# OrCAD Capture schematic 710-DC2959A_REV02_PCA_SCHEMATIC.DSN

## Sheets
1 PAGE4: size Custom
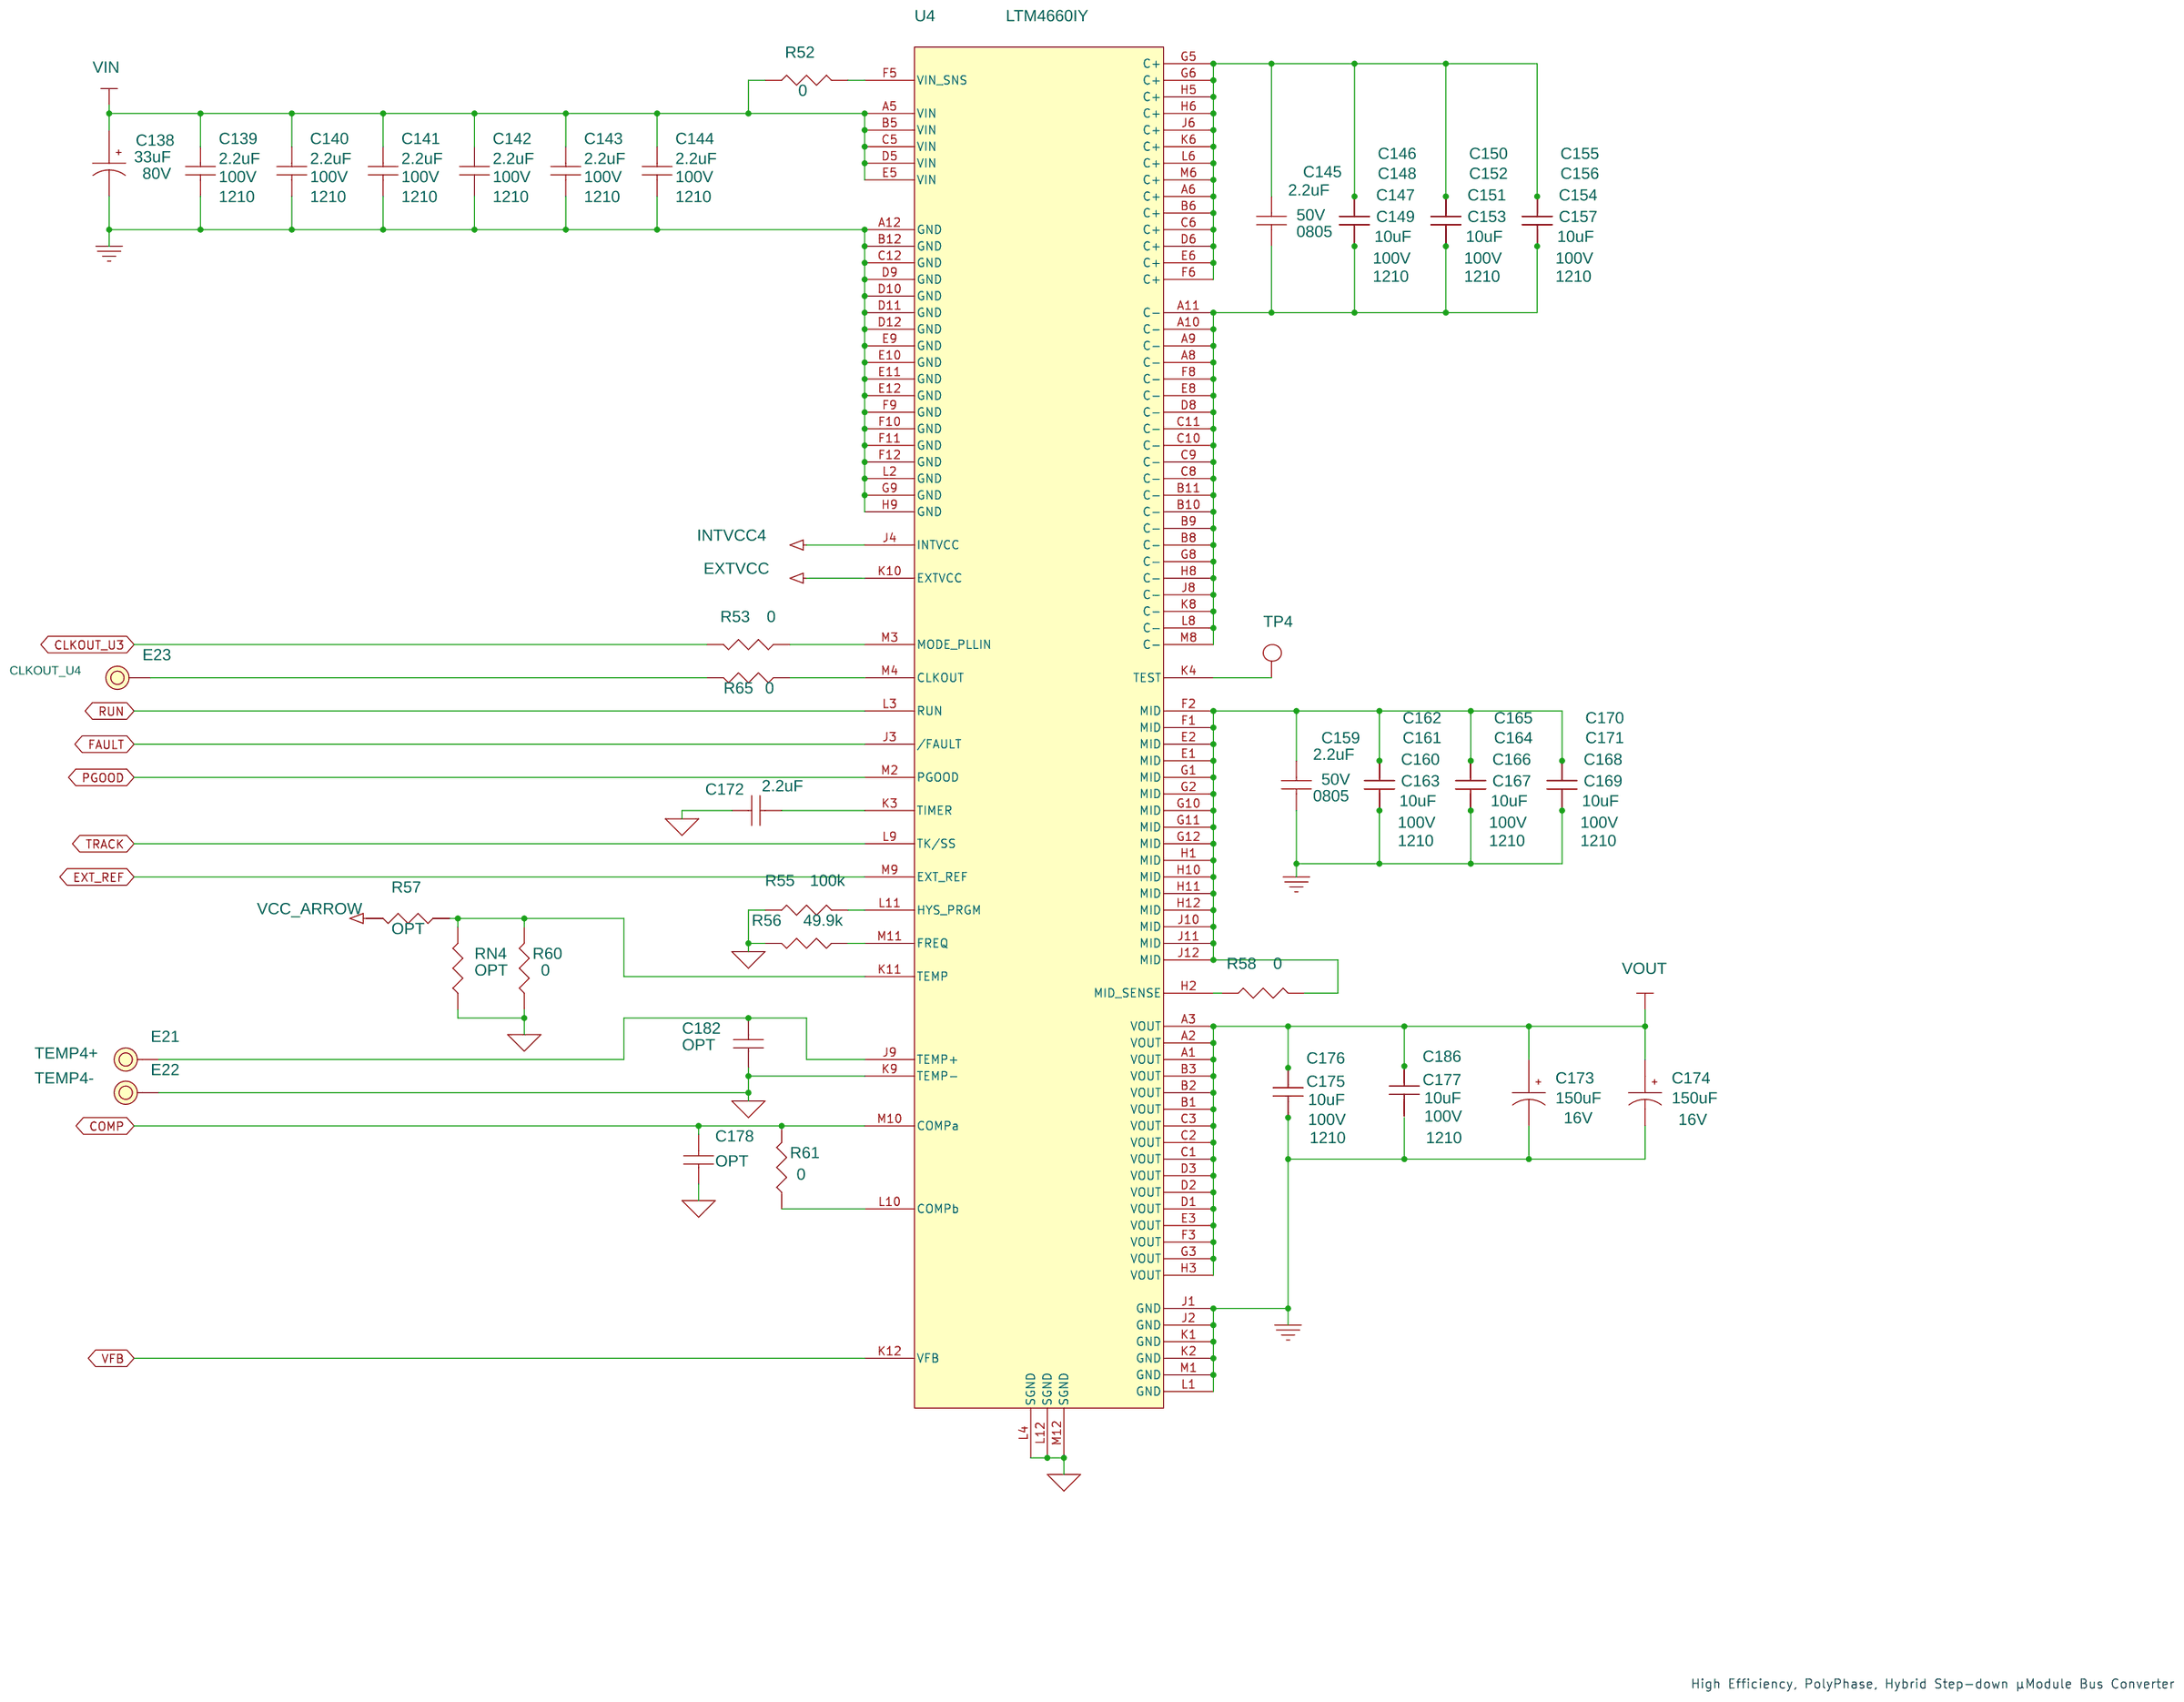
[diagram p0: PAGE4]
2 PAGE3: size Custom
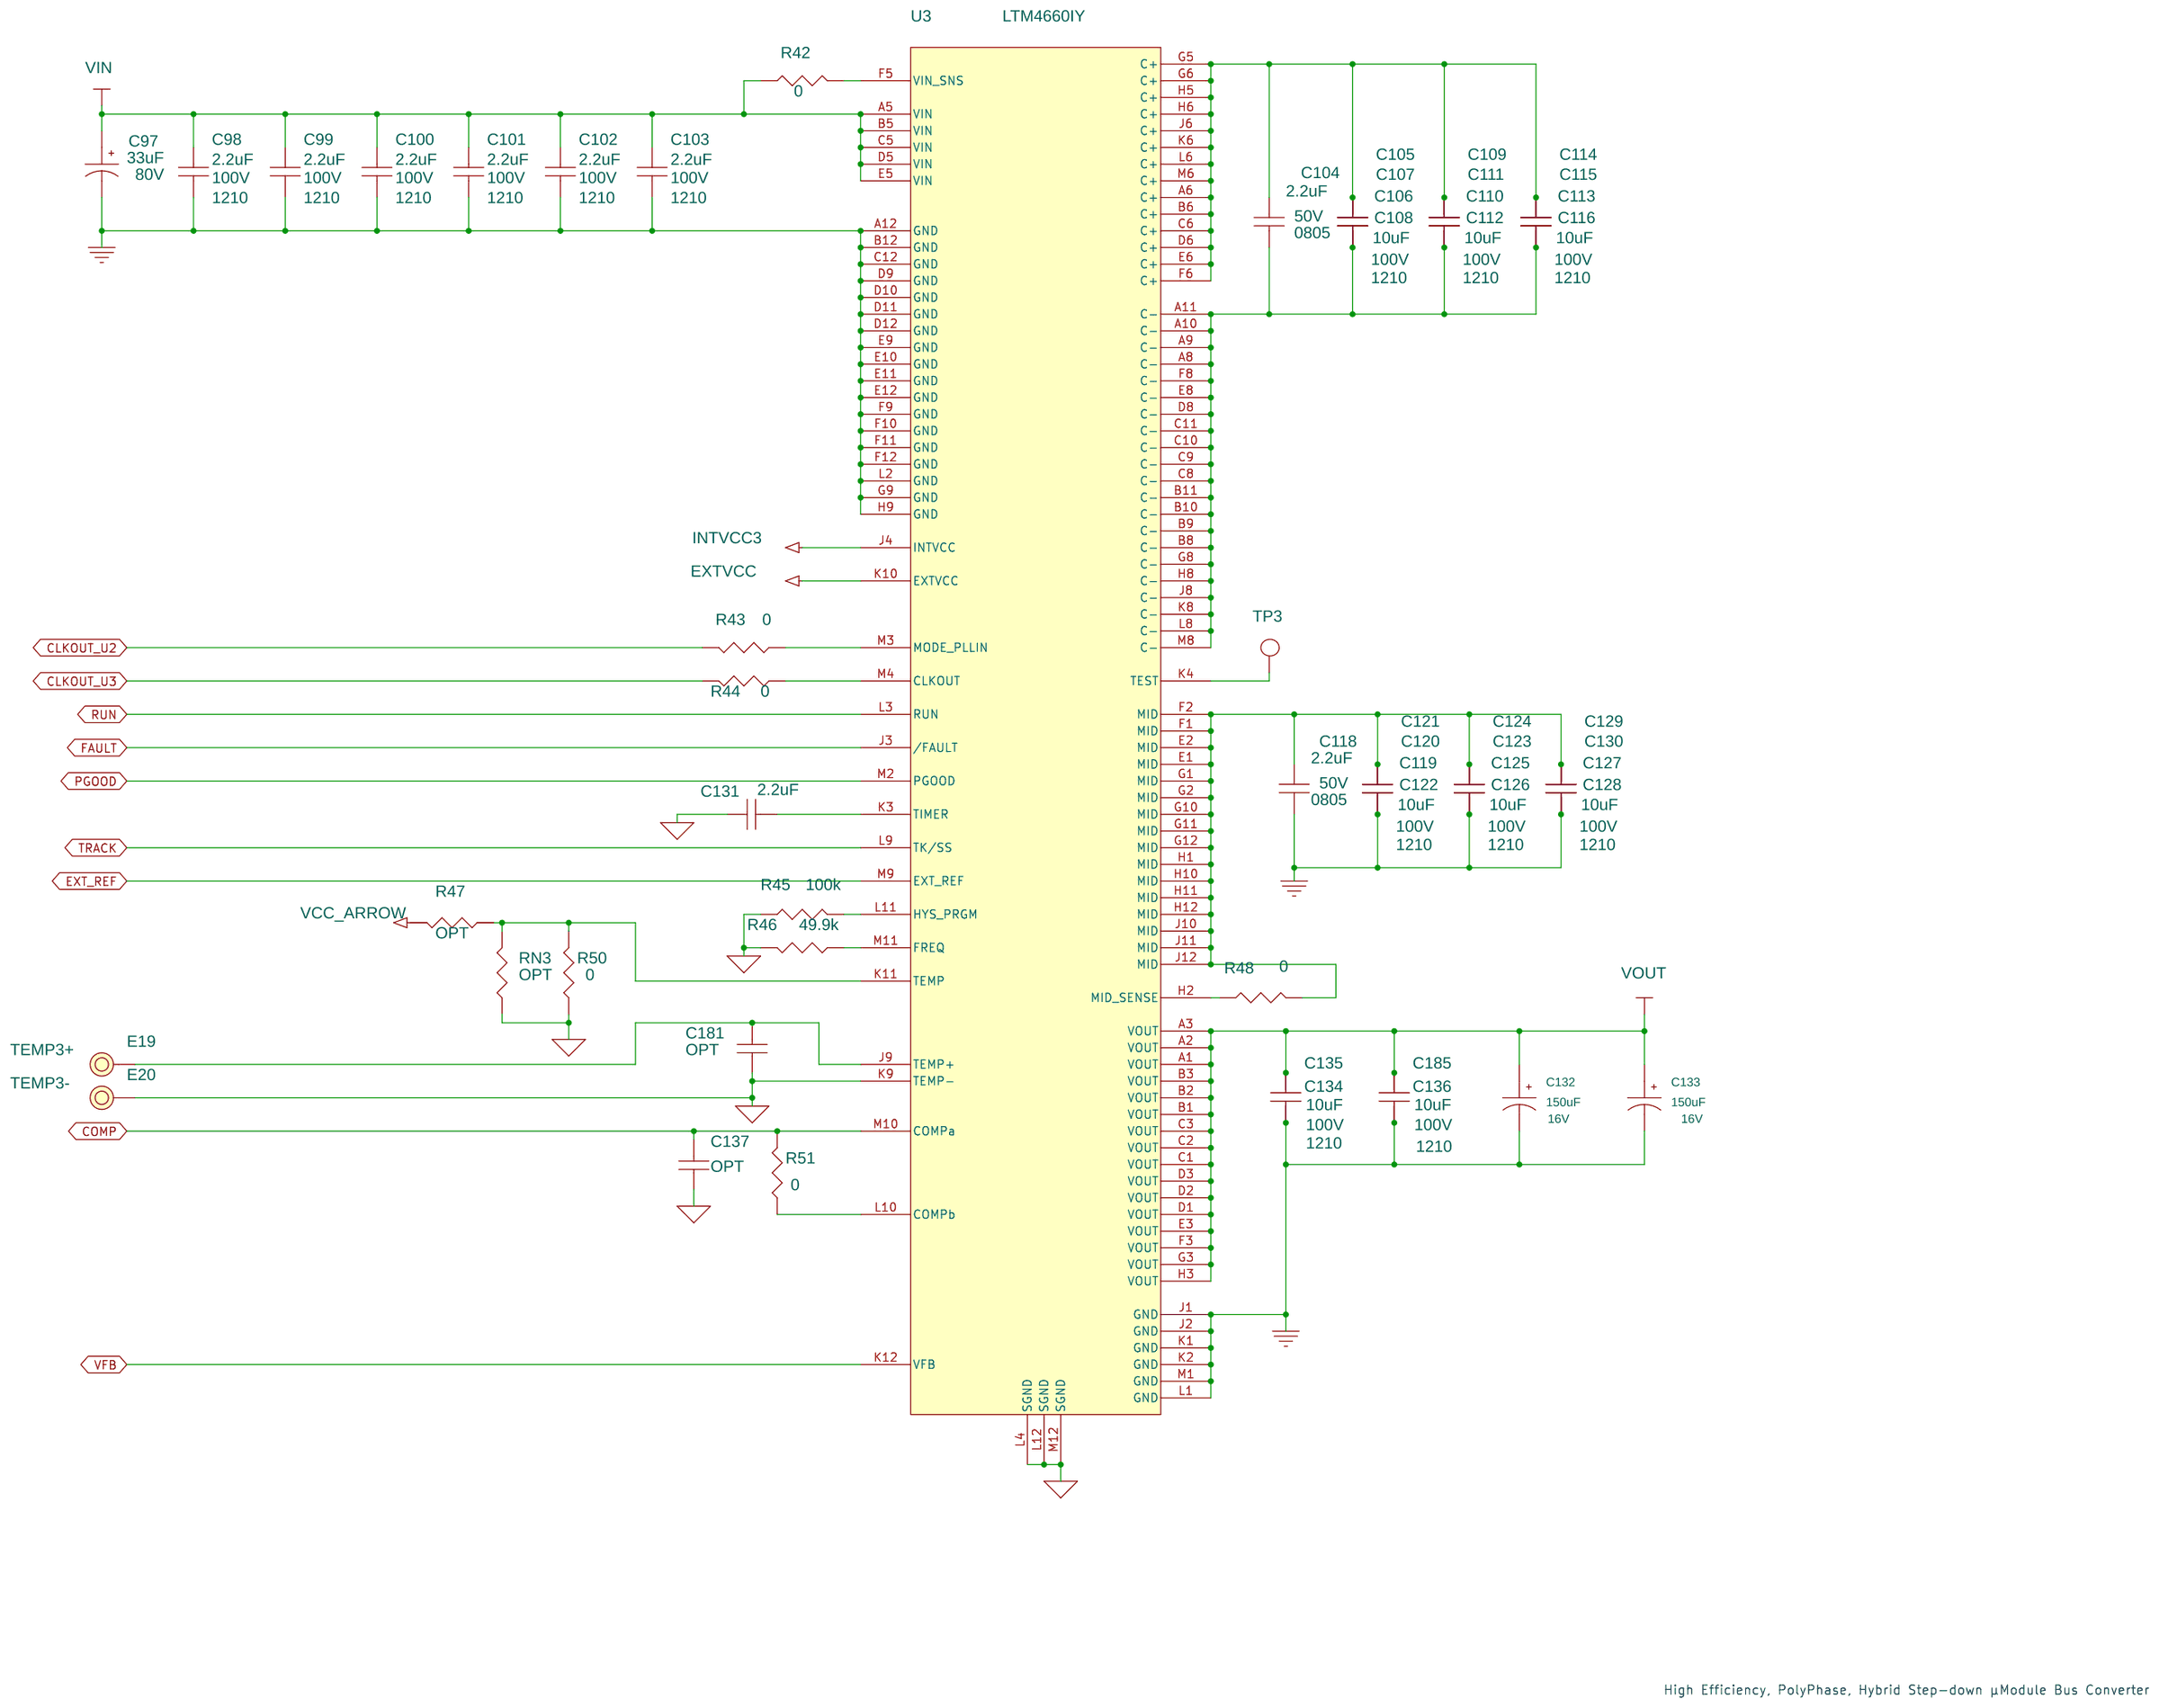
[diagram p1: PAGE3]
3 PAGE2: size Custom
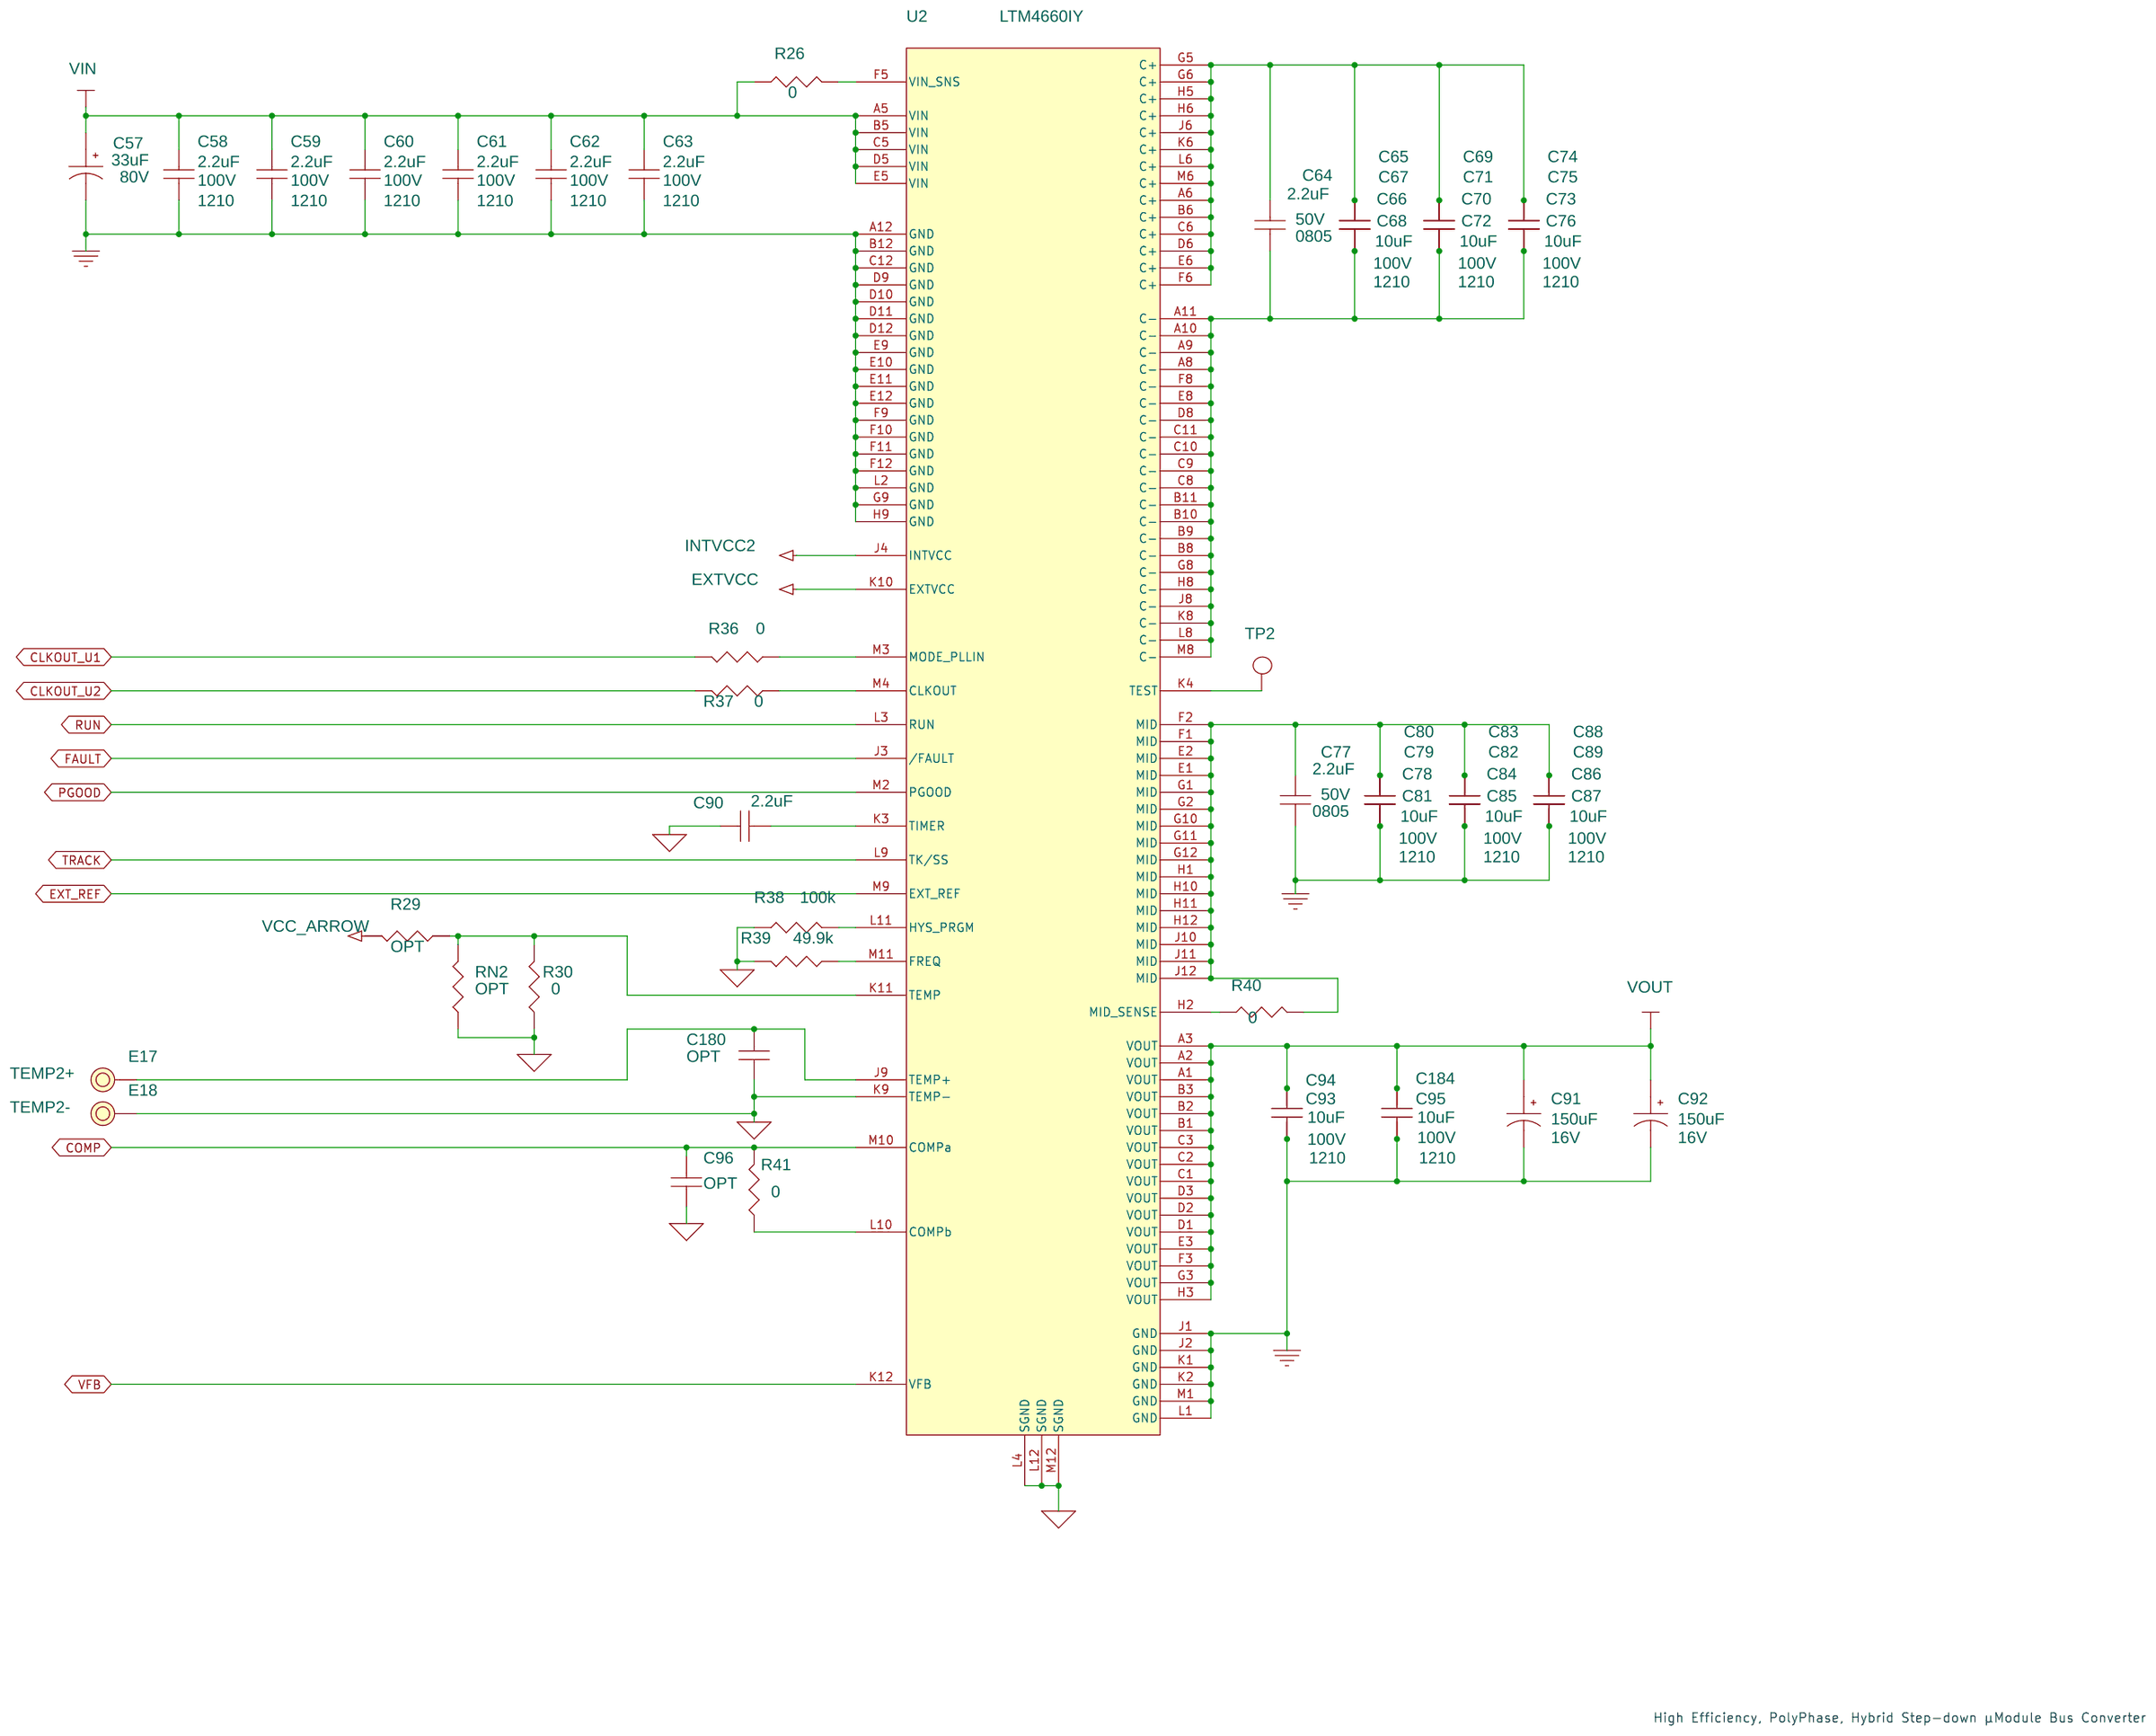
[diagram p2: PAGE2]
4 PAGE6: size A
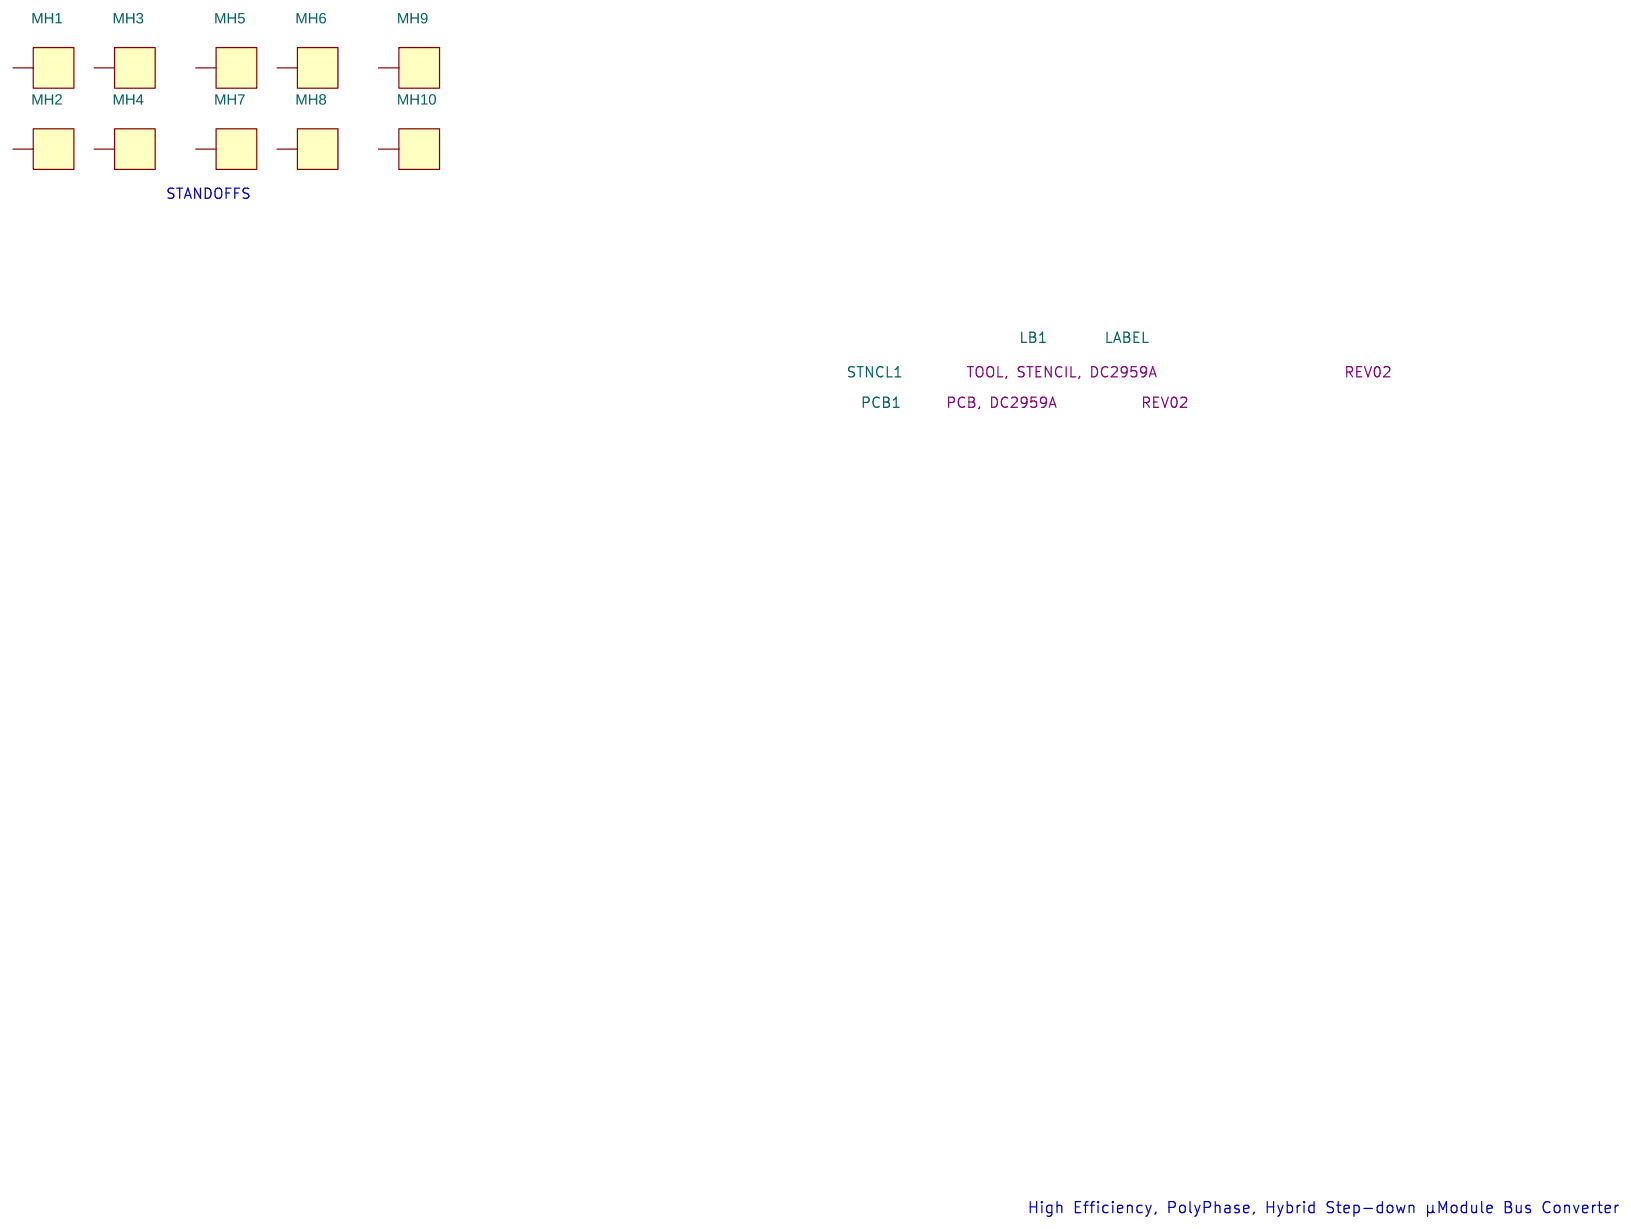
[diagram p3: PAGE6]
5 PAGE5: size Custom
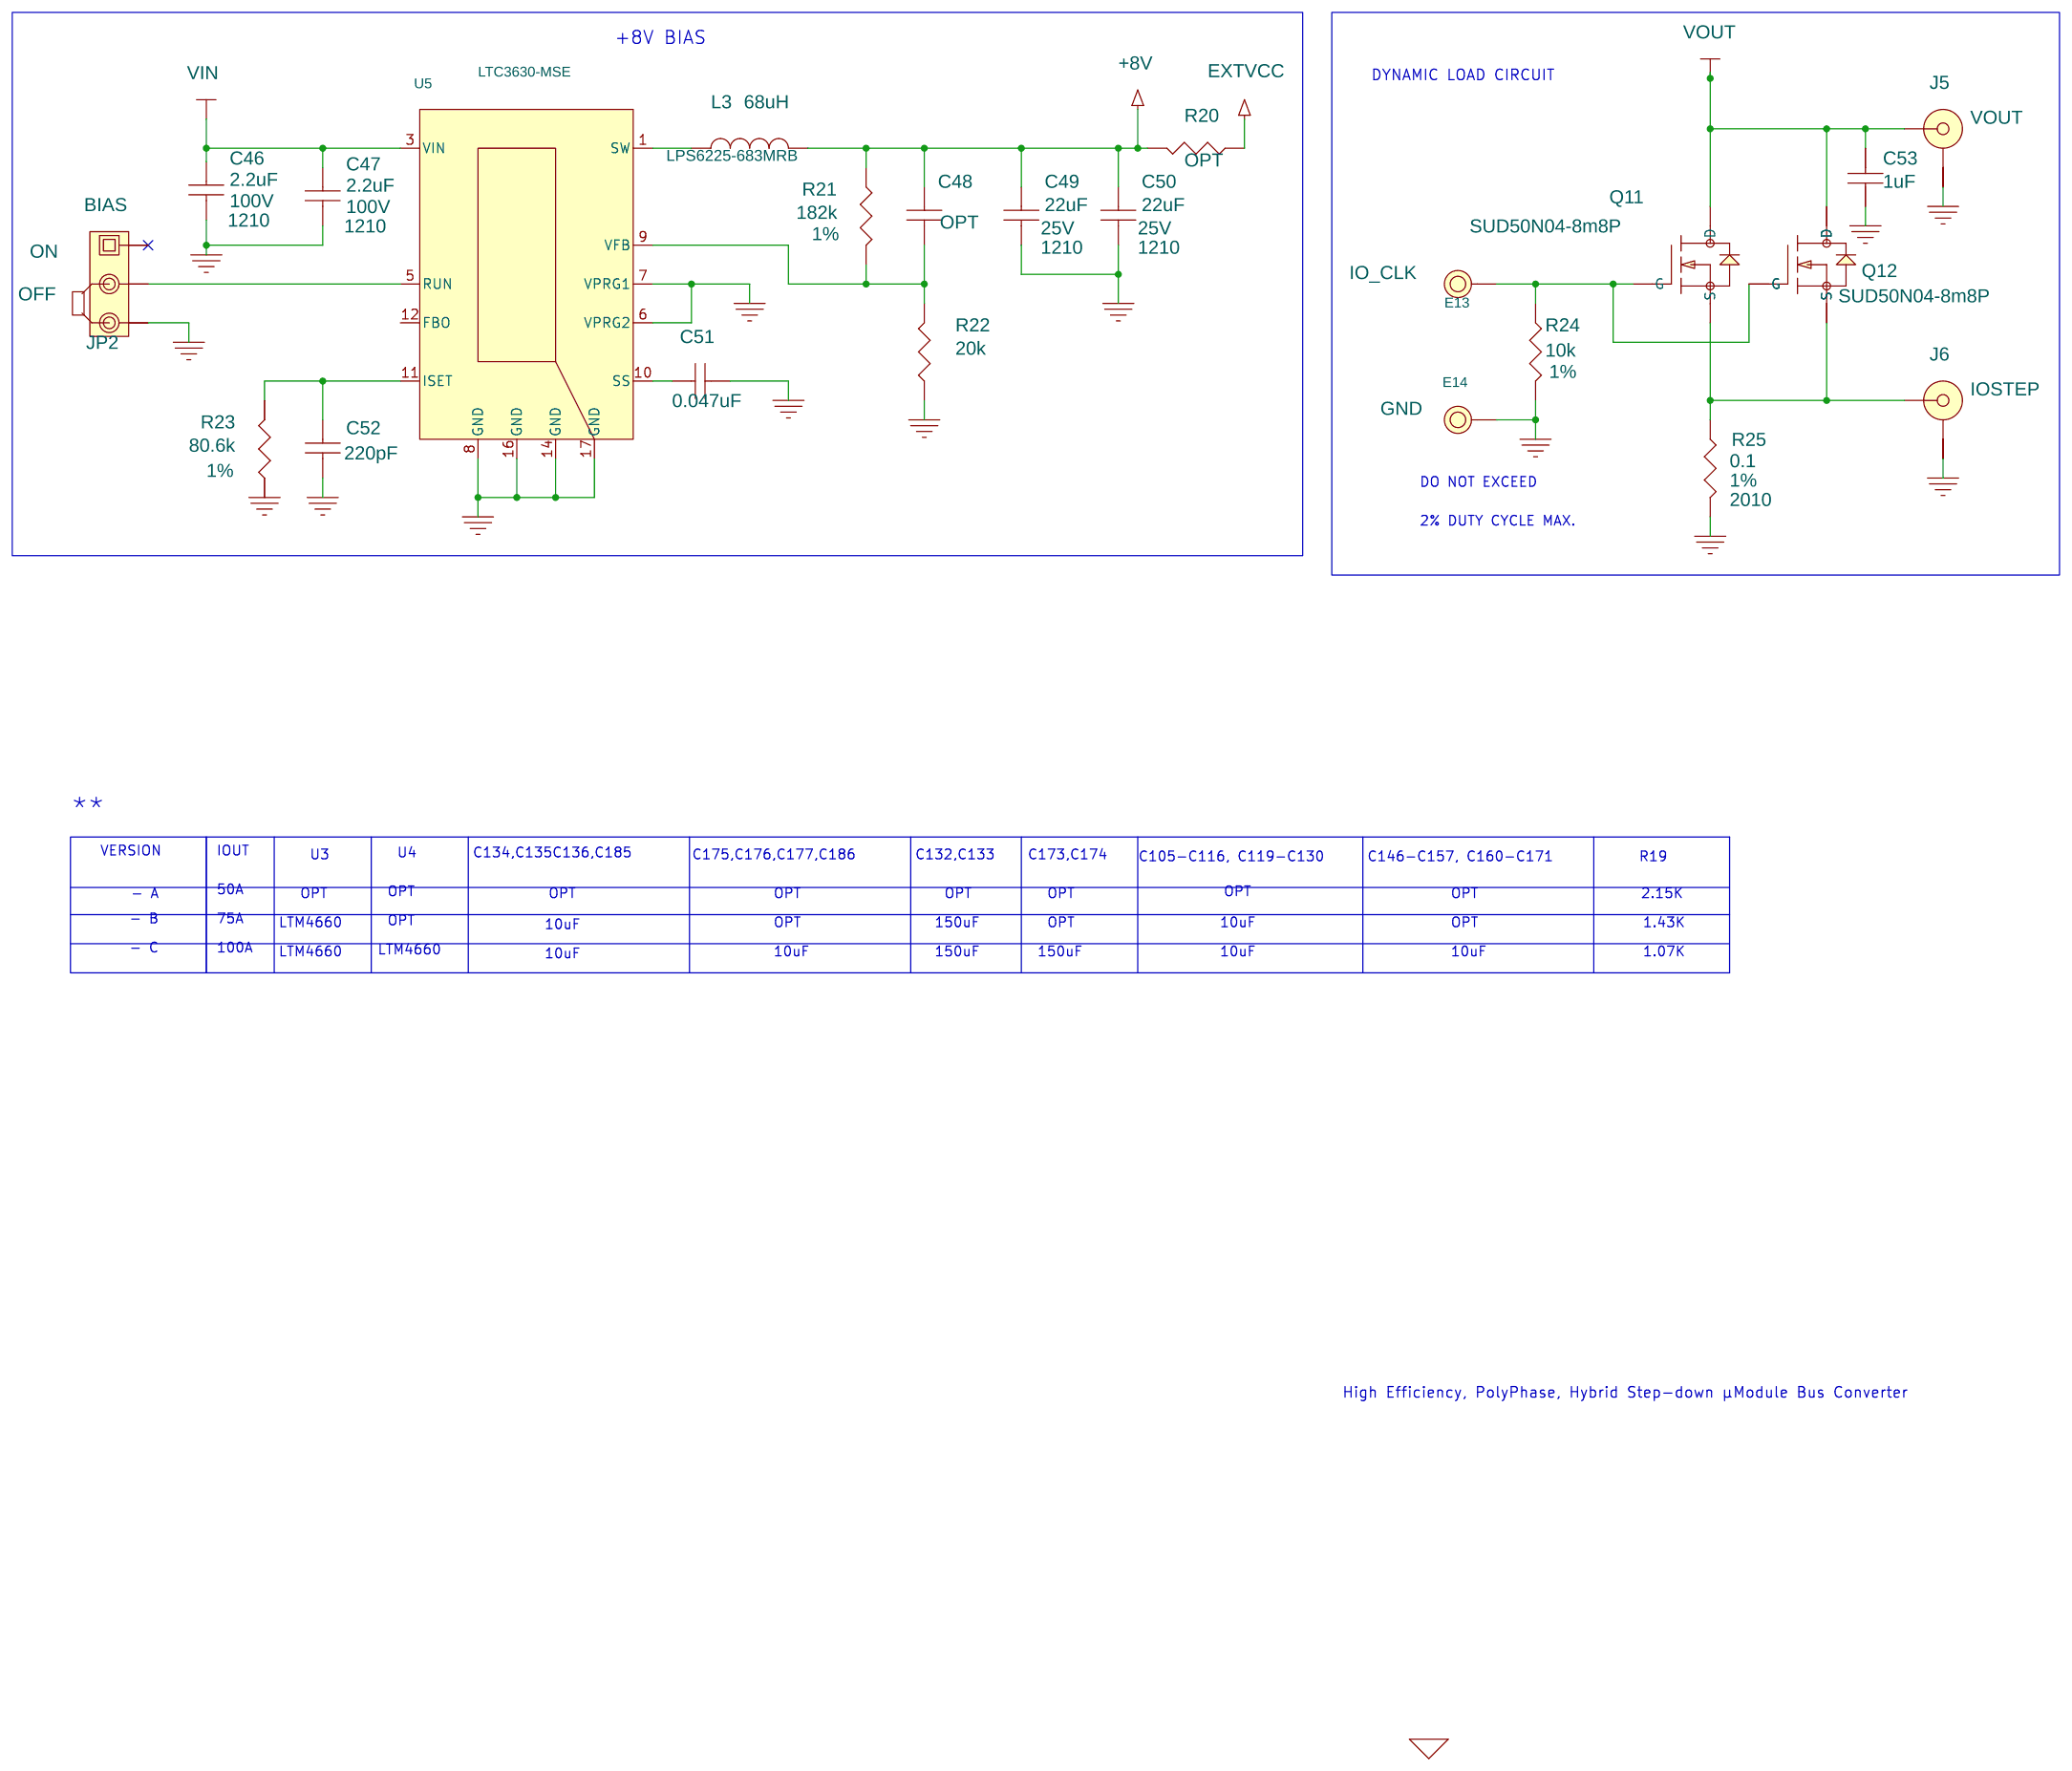
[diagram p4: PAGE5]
6 PAGE1: size Custom
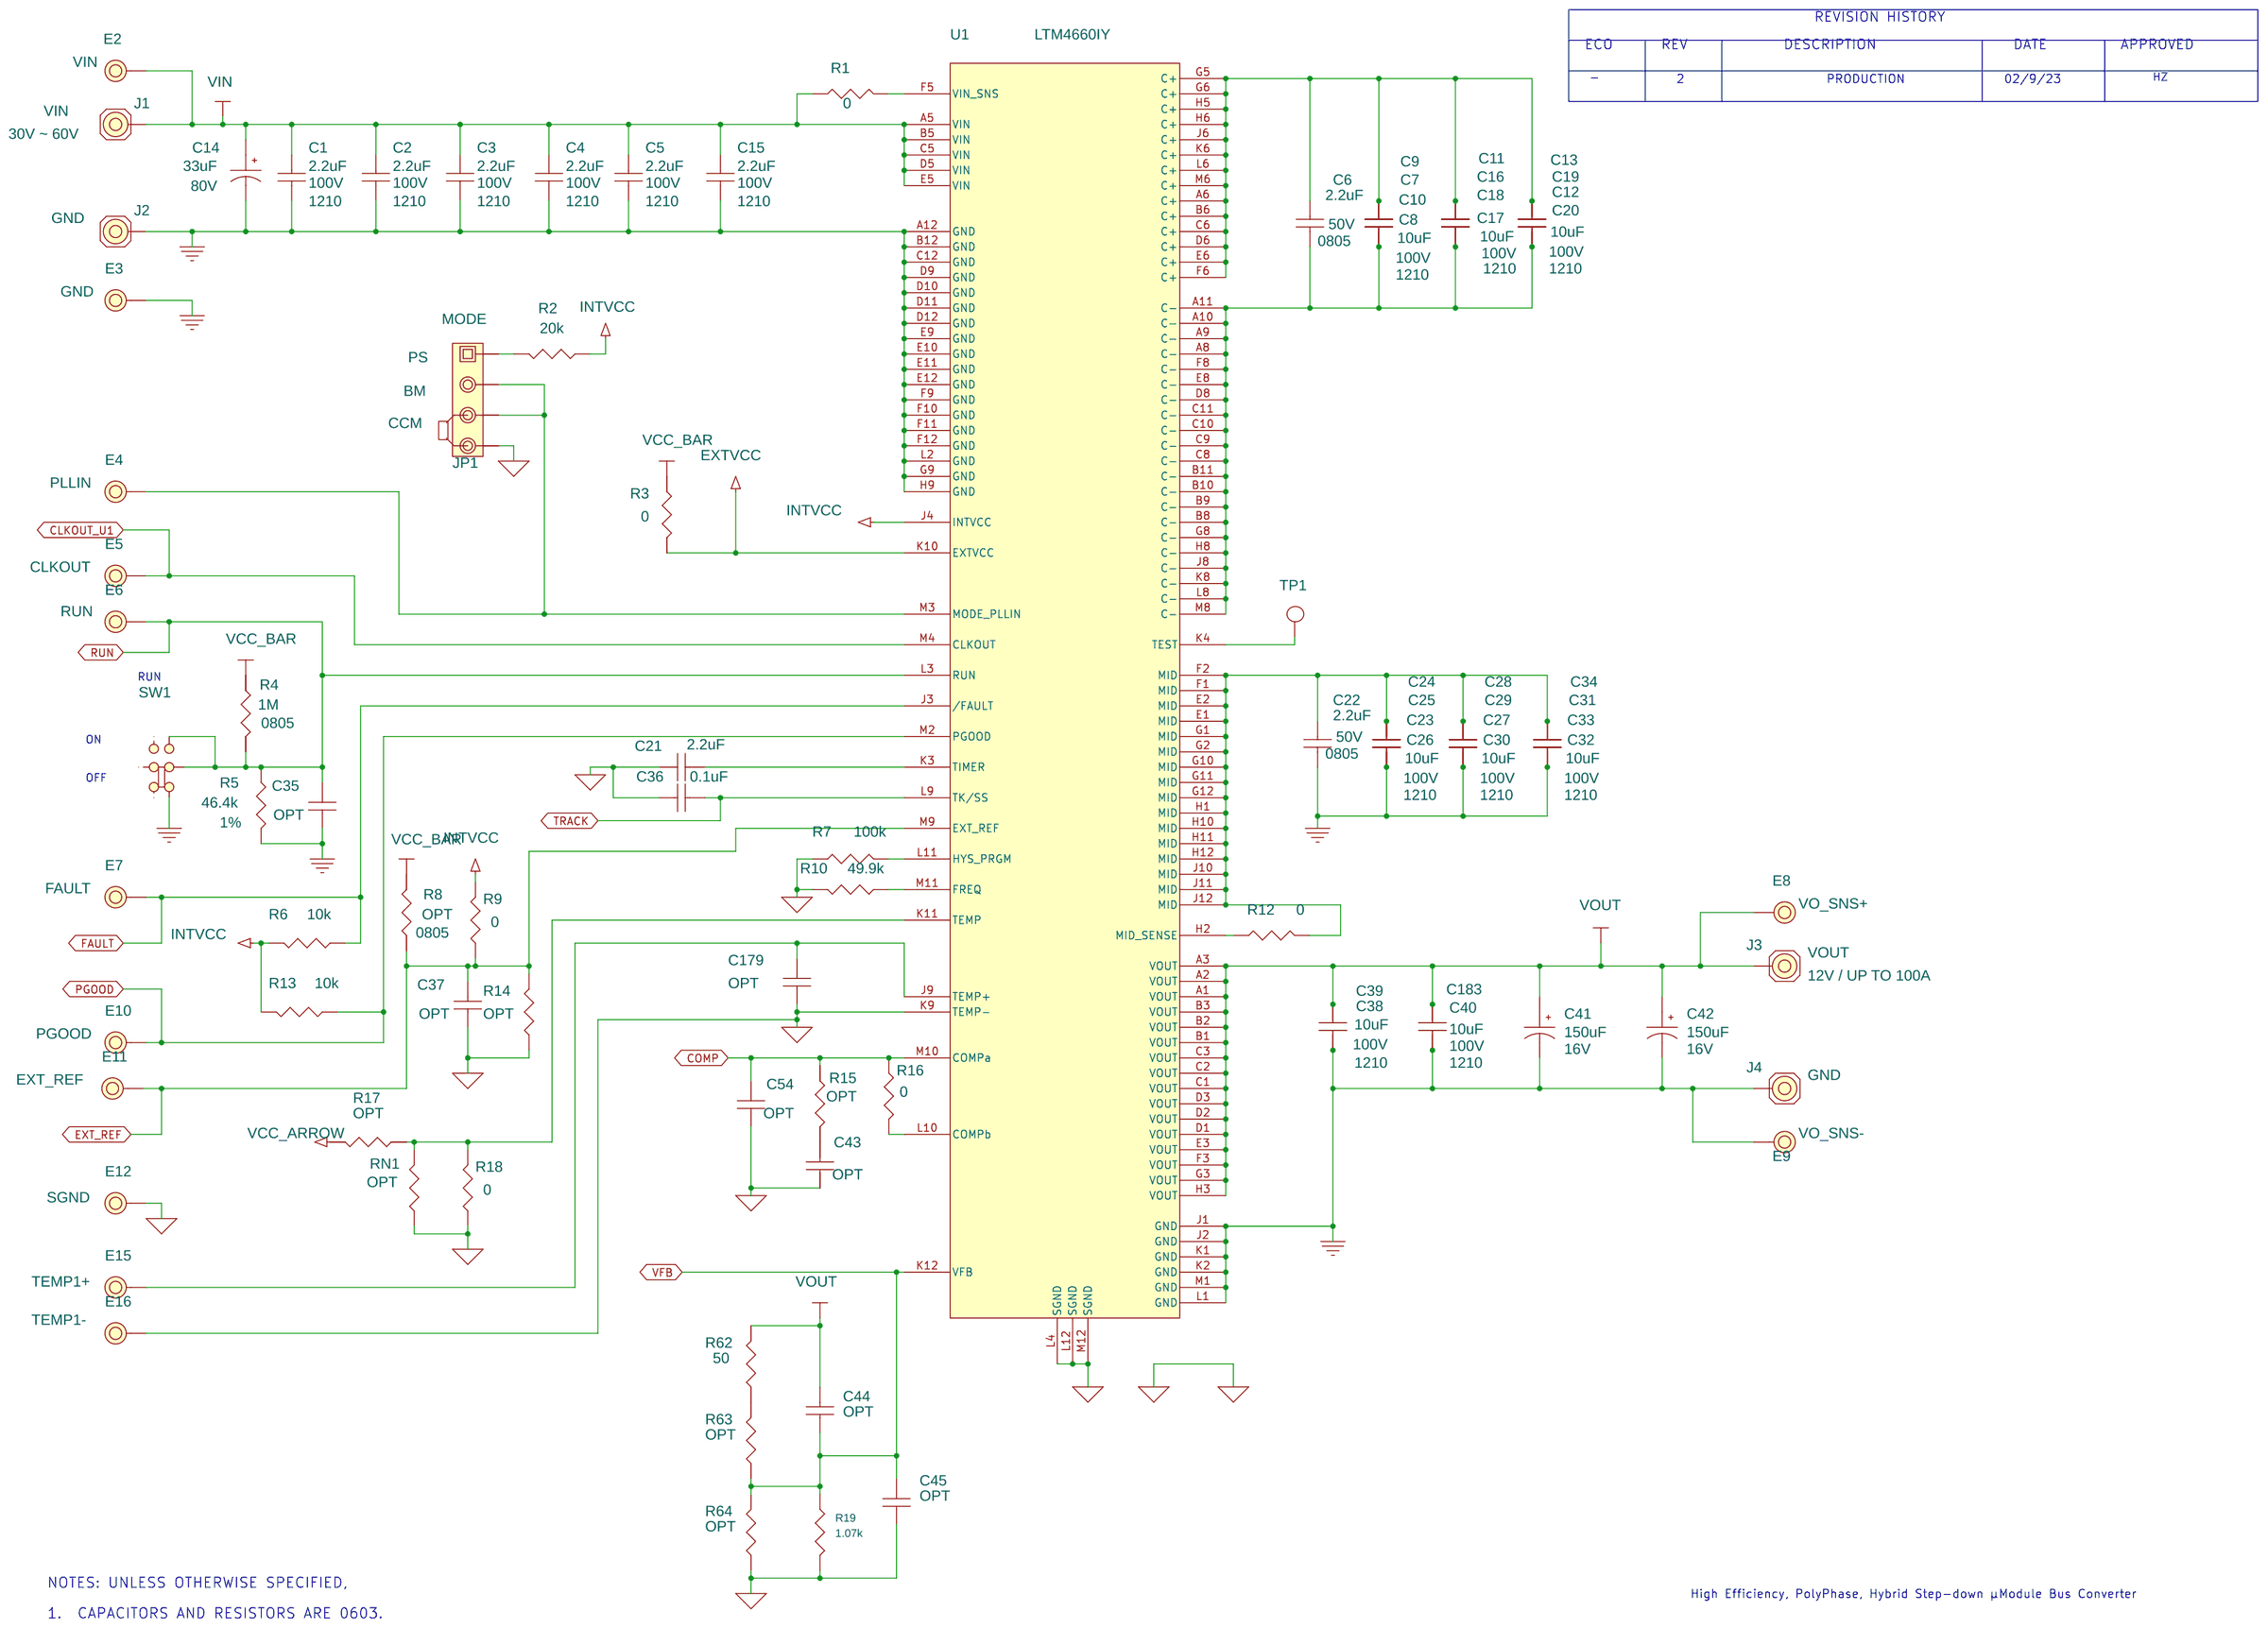
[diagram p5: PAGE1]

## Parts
sheet PAGE1
C1  2.2uF  [CC1210N]
C2  2.2uF  [CC1210N]
C3  2.2uF  [CC1210N]
C4  2.2uF  [CC1210N]
C5  2.2uF  [CC1210N]
C6  2.2uF  [CC0805N]
C7  10uF  [CC1210N]
C8  10uF  [CC1210N]
C9  10uF  [CC1210N]
C10  10uF  [CC1210N]
C11  10uF  [CC1210N]
C12  10uF  [CC1210N]
C13  10uF  [CC1210N]
C14  33uF  [PANASONIC_ZA_10X10.2]
C15  2.2uF  [CC1210N]
C16  10uF  [CC1210N]
C17  10uF  [CC1210N]
C18  10uF  [CC1210N]
C19  10uF  [CC1210N]
C20  10uF  [CC1210N]
C21  2.2uF  [CC0603N]
C22  2.2uF  [CC0805N]
C23  10uF  [CC1210N]
C24  10uF  [CC1210N]
C25  10uF  [CC1210N]
C26  10uF  [CC1210N]
C27  10uF  [CC1210N]
C28  10uF  [CC1210N]
C29  10uF  [CC1210N]
C30  10uF  [CC1210N]
C31  10uF  [CC1210N]
C32  10uF  [CC1210N]
C33  10uF  [CC1210N]
C34  10uF  [CC1210N]
C35  OPT  [CC0603N]
C36  0.1uF  [CC0603N]
C37  OPT  [CC0603N]
C38  10uF  [CC1210N]
C39  10uF  [CC1210N]
C40  10uF  [CC1210N]
C41  150uF  [PANASONIC_SVPC_8X6.9]
C42  150uF  [PANASONIC_SVPC_8X6.9]
C43  OPT  [CC0603N]
C44  OPT  [CC0603N]
C45  OPT  [CC0603N]
C54  OPT  [CC0603N]
C179  OPT  [CC0603N]
C183  10uF  [CC1210N]
E2  TEST POINT  [MILLMAX2501]
E3  TEST POINT  [MILLMAX2501]
E4  TEST POINT  [MILLMAX2501]
E5  TEST POINT  [MILLMAX2501]
E6  TEST POINT  [MILLMAX2501]
E7  TEST POINT  [MILLMAX2501]
E8  TEST POINT  [MILLMAX2501]
E9  TEST POINT  [MILLMAX2501]
E10  TEST POINT  [MILLMAX2501]
E11  TEST POINT  [MILLMAX2501]
E12  TEST POINT  [MILLMAX2501]
E15  TEST POINT  [MILLMAX2501]
E16  TEST POINT  [MILLMAX2501]
J1  STUD,#10-32  [PENN-KFH-032]
J2  STUD,#10-32  [PENN-KFH-032]
J3  STUD,#10-32  [PENN-KFH-032]
J4  STUD,#10-32  [PENN-KFH-032]
JP1  HDR  [HD1X4-079]
R1  0  [CR0603N]
R2  20k  [CR0603N]
R3  0  [CR0603N]
R4  1M  [CR0805N]
R5  46.4k  [CR0603N]
R6  10k  [CR0603N]
R7  100k  [CR0603N]
R8  OPT  [CR0805N]
R9  0  [CR0603N]
R10  49.9k  [CR0603N]
R12  0  [CR0603N]
R13  10k  [CR0603N]
R14  OPT  [CR0603N]
R15  OPT  [CR0603N]
R16  0  [CR0603N]
R17  OPT  [CR0603N]
R18  0  [CR0603N]
R19  1.07k  [CR0603N]
R62  50  [CR0603N]
R63  OPT  [CR0603N]
R64  OPT  [CR0603N]
RN1  OPT  [CR0603N]
SW1  DPDT  [CK-JS202011CQN]
TP1  TESTPAD  [PAD]
U1  LTM4660-BGA  [LTC-BGA-120-1623]
XJP1  SHUNT
sheet PAGE2
C57  33uF  [PANASONIC_ZA_10X10.2]
C58  2.2uF  [CC1210N]
C59  2.2uF  [CC1210N]
C60  2.2uF  [CC1210N]
C61  2.2uF  [CC1210N]
C62  2.2uF  [CC1210N]
C63  2.2uF  [CC1210N]
C64  2.2uF  [CC0805N]
C65  10uF  [CC1210N]
C66  10uF  [CC1210N]
C67  10uF  [CC1210N]
C68  10uF  [CC1210N]
C69  10uF  [CC1210N]
C70  10uF  [CC1210N]
C71  10uF  [CC1210N]
C72  10uF  [CC1210N]
C73  10uF  [CC1210N]
C74  10uF  [CC1210N]
C75  10uF  [CC1210N]
C76  10uF  [CC1210N]
C77  2.2uF  [CC0805N]
C78  10uF  [CC1210N]
C79  10uF  [CC1210N]
C80  10uF  [CC1210N]
C81  10uF  [CC1210N]
C82  10uF  [CC1210N]
C83  10uF  [CC1210N]
C84  10uF  [CC1210N]
C85  10uF  [CC1210N]
C86  10uF  [CC1210N]
C87  10uF  [CC1210N]
C88  10uF  [CC1210N]
C89  10uF  [CC1210N]
C90  2.2uF  [CC0603N]
C91  150uF  [PANASONIC_SVPC_8X6.9]
C92  150uF  [PANASONIC_SVPC_8X6.9]
C93  10uF  [CC1210N]
C94  10uF  [CC1210N]
C95  10uF  [CC1210N]
C96  OPT  [CC0603N]
C180  OPT  [CC0603N]
C184  10uF  [CC1210N]
E17  TEST POINT  [MILLMAX2501]
E18  TEST POINT  [MILLMAX2501]
R26  0  [CR0603N]
R29  OPT  [CR0603N]
R30  0  [CR0603N]
R36  0  [CR0603N]
R37  0  [CR0603N]
R38  100k  [CR0603N]
R39  49.9k  [CR0603N]
R40  0  [CR0603N]
R41  0  [CR0603N]
RN2  OPT  [CR0603N]
TP2  TESTPAD  [PAD]
U2  LTM4660-BGA  [LTC-BGA-120-1623]
sheet PAGE3
C97  33uF  [PANASONIC_ZA_10X10.2]
C98  2.2uF  [CC1210N]
C99  2.2uF  [CC1210N]
C100  2.2uF  [CC1210N]
C101  2.2uF  [CC1210N]
C102  2.2uF  [CC1210N]
C103  2.2uF  [CC1210N]
C104  2.2uF  [CC0805N]
C105  10uF  [CC1210N]
C106  10uF  [CC1210N]
C107  10uF  [CC1210N]
C108  10uF  [CC1210N]
C109  10uF  [CC1210N]
C110  10uF  [CC1210N]
C111  10uF  [CC1210N]
C112  10uF  [CC1210N]
C113  10uF  [CC1210N]
C114  10uF  [CC1210N]
C115  10uF  [CC1210N]
C116  10uF  [CC1210N]
C118  2.2uF  [CC0805N]
C119  10uF  [CC1210N]
C120  10uF  [CC1210N]
C121  10uF  [CC1210N]
C122  10uF  [CC1210N]
C123  10uF  [CC1210N]
C124  10uF  [CC1210N]
C125  10uF  [CC1210N]
C126  10uF  [CC1210N]
C127  10uF  [CC1210N]
C128  10uF  [CC1210N]
C129  10uF  [CC1210N]
C130  10uF  [CC1210N]
C131  2.2uF  [CC0603N]
C132  150uF  [PANASONIC_SVPC_8X6.9]
C133  150uF  [PANASONIC_SVPC_8X6.9]
C134  10uF  [CC1210N]
C135  10uF  [CC1210N]
C136  10uF  [CC1210N]
C137  OPT  [CC0603N]
C181  OPT  [CC0603N]
C185  10uF  [CC1210N]
E19  TEST POINT  [MILLMAX2501]
E20  TEST POINT  [MILLMAX2501]
R42  0  [CR0603N]
R43  0  [CR0603N]
R44  0  [CR0603N]
R45  100k  [CR0603N]
R46  49.9k  [CR0603N]
R47  OPT  [CR0603N]
R48  0  [CR0603N]
R50  0  [CR0603N]
R51  0  [CR0603N]
RN3  OPT  [CR0603N]
TP3  TESTPAD  [PAD]
U3  LTM4660-BGA  [LTC-BGA-120-1623]
sheet PAGE4
C138  33uF  [PANASONIC_ZA_10X10.2]
C139  2.2uF  [CC1210N]
C140  2.2uF  [CC1210N]
C141  2.2uF  [CC1210N]
C142  2.2uF  [CC1210N]
C143  2.2uF  [CC1210N]
C144  2.2uF  [CC1210N]
C145  2.2uF  [CC0805N]
C146  10uF  [CC1210N]
C147  10uF  [CC1210N]
C148  10uF  [CC1210N]
C149  10uF  [CC1210N]
C150  10uF  [CC1210N]
C151  10uF  [CC1210N]
C152  10uF  [CC1210N]
C153  10uF  [CC1210N]
C154  10uF  [CC1210N]
C155  10uF  [CC1210N]
C156  10uF  [CC1210N]
C157  10uF  [CC1210N]
C159  2.2uF  [CC0805N]
C160  10uF  [CC1210N]
C161  10uF  [CC1210N]
C162  10uF  [CC1210N]
C163  10uF  [CC1210N]
C164  10uF  [CC1210N]
C165  10uF  [CC1210N]
C166  10uF  [CC1210N]
C167  10uF  [CC1210N]
C168  10uF  [CC1210N]
C169  10uF  [CC1210N]
C170  10uF  [CC1210N]
C171  10uF  [CC1210N]
C172  2.2uF  [CC0603N]
C173  150uF  [PANASONIC_SVPC_8X6.9]
C174  150uF  [PANASONIC_SVPC_8X6.9]
C175  10uF  [CC1210N]
C176  10uF  [CC1210N]
C177  10uF  [CC1210N]
C178  OPT  [CC0603N]
C182  OPT  [CC0603N]
C186  10uF  [CC1210N]
E21  TEST POINT  [MILLMAX2501]
E22  TEST POINT  [MILLMAX2501]
E23  TEST POINT  [MILLMAX2501]
R52  0  [CR0603N]
R53  0  [CR0603N]
R55  100k  [CR0603N]
R56  49.9k  [CR0603N]
R57  OPT  [CR0603N]
R58  0  [CR0603N]
R60  0  [CR0603N]
R61  0  [CR0603N]
R65  0  [CR0603N]
RN4  OPT  [CR0603N]
TP4  TESTPAD  [PAD]
U4  LTM4660-BGA  [LTC-BGA-120-1623]
sheet PAGE5
C46  2.2uF  [CC1210N]
C47  2.2uF  [CC1210N]
C48  OPT  [CC0603N]
C49  22uF  [CC1210N]
C50  22uF  [CC1210N]
C51  0.047uF  [CC0603N]
C52  220pF  [CC0603N]
C53  1uF  [CC0603N]
E13  TEST POINT  [MILLMAX2501]
E14  TEST POINT  [MILLMAX2501]
J5  RF,BNC  [CONNEX-112404]
J6  RF,BNC  [CONNEX-112404]
JP2  HDR  [HD1X3-079]
L3  68uH  [COILCRAFT-LPS6225]
Q11  SUD50N04-8m8P  [TO-252-3N]
Q12  SUD50N04-8m8P  [TO-252-3N]
R20  OPT  [CR0603N]
R21  182k  [CR0603N]
R22  20k  [CR0603N]
R23  80.6k  [CR0603N]
R24  10k  [CR0603N]
R25  0.1  [CR2010N]
U5  LTC3630-MSE  [LTC-MSE-16-1871]
XJP2  SHUNT
sheet PAGE6
LB1  LABEL  [895-0154_REV01]
MH1  STANDOFF  [KEYSTONE_8829-8834]
MH2  STANDOFF  [KEYSTONE_8829-8834]
MH3  STANDOFF  [KEYSTONE_8829-8834]
MH4  STANDOFF  [KEYSTONE_8829-8834]
MH5  STANDOFF  [KEYSTONE_8829-8834]
MH6  STANDOFF  [KEYSTONE_8829-8834]
MH7  STANDOFF  [KEYSTONE_8829-8834]
MH8  STANDOFF  [KEYSTONE_8829-8834]
MH9  STANDOFF  [KEYSTONE_8829-8834]
MH10  STANDOFF  [KEYSTONE_8829-8834]
PCB1  PCB, DC2959A  [MECHANICAL_PART]
STNCL1  TOOL, STENCIL, DC2959A

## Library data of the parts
C1-C5 C15 C46 C47 C58-C63 C98-C103 C139-C144 = CAP: CAP.,2.2uF,X7R,100V,10%,1210; CLASS: DISCRETE; Dielectric Type: X7R; FPLIST: CC1210N,CC1210L,CC1210M; Inventory Qty: 19274; Manufacturer: AVX; Manufacturer PN: 12101C225KAT2A; PART_NUMBER: 150-2506; Package Size: 1210; Part Number: MURATA GRM32DR72A225KA12K; Rated Voltage: 100V; Tolerance: 10%
C6 C22 C64 C77 C104 C118 C145 C159 = CAP: CAP.,2.2uF,X7R,50V,10%,0805; CLASS: DISCRETE; Dielectric Type: X7R; FPLIST: CC0805N,CC0805L,CC0805M; Inventory Qty: 12348; Manufacturer: AVX; Manufacturer PN: 08055C225KAT2A; PART_NUMBER: 150-0578; Package Size: 0805; Rated Voltage: 50V; Tolerance: 10%
C7-C13 C16-C20 C23-C34 C38-C40 C65-C76 C78-C89 C93-C95 C105-C116 C119-C130 C134-C136 C146-C157 C160-C171 C175-C177 C183-C186 = CAP: CAP.,10uF,X7S,100V,10%,1210; CLASS: DISCRETE; Dielectric Type: X7S; FPLIST: CC1210N,CC1210L,CC1210M; Inventory Qty: 26843; Manufacturer: MURATA; Manufacturer PN: GRM32EC72A106KE05L; PART_NUMBER: 150-2537; Package Size: 1210; Package Type: Surface Mount, MLCC; Rated Voltage: 100V; Temperature Coefficient: X7S; Tolerance: 10%
C14 C57 C97 C138 = CAP_P: CAP.,33uF,ALUM. POLY. HYB.,80V,20%,10x10.2mm SMD, RADIAL,AEC-Q200; CLASS: DISCRETE; Dielectric Type: ALUM. POLY. HYB.; Inventory Qty: 10657; Manufacturer: PANASONIC; Manufacturer PN: EEHZA1K330P; PART_NUMBER: 150-2503; Package Size: 10x10.2mm SMD, RADIAL; Part Number: PANASONIC EEHZA1K330P; Rated Voltage: 80V; Tolerance: 20%
C21 C90 C131 C172 = CAP: CAP.,2.2uF,X7S,25V,10%,0603; CLASS: DISCRETE; Dielectric Type: X7S; Inventory Qty: 20000; Manufacturer: MURATA; Manufacturer PN: GRM188C71E225KE11D; PART_NUMBER: 150-1812; Package Size: 0603; Rated Voltage: 25V; Temperature Coefficient: X7S; Tolerance: 10%
C35 C37 C43-C45 C48 C54 C96 C137 C178-C182 = CAP: CAP., OPTION, 0603; CLASS: DISCRETE; FPLIST: CC0603N,CC0603L,CC0603M; PART_NUMBER: 150-3038; Package Size: 0603; Package Type: SMD; Part Number: OPTION; UserField01: OPTION
C36 = CAP: CAP.,0.1uF,X7S,100V,10%,0603; CLASS: DISCRETE; Dielectric Type: X7S; FPLIST: CC0603N,CC0603L,CC0603M; Inventory Qty: 22002; Manufacturer: TAIYO YUDEN; Manufacturer PN: HMK107C7104KA-T; PART_NUMBER: 150-0493; Package Size: 0603; Part Number: MURATA GRM188R72A104KA35D; Rated Voltage: 100V; Tolerance: 10%
C41 C42 C91 C92 C132 C133 C173 C174 = CAP_P: CAP.,150uF,ALUM., OS-CON,16V,20%,8x6.9mm SMD, RADIAL; CLASS: DISCRETE; Dielectric Type: ALUM., OS-CON; Inventory Qty: 7506; Manufacturer: PANASONIC; Manufacturer PN: 16SVPC150M; PART_NUMBER: 150-2273; Package Size: 8x6.9mm SMD, RADIAL; Part Number: PANASONIC 16SVPC150M; Rated Voltage: 16V; Tolerance: 20%
E2 = TESTPOINT_.219_MILL-MAX_2501: TEST POINT,TURRET,0.094" MTG. HOLE,PCB 0.062" THK; CLASS: IO; Inventory Qty: 609555; Label1: VIN; Label2: 14V MAX; Manufacturer: MILL-MAX; Manufacturer PN: 2501-2-00-80-00-00-07-0; PART_NUMBER: 260-0003; Part Number: MILL-MAX 2501-2-00-80-00-00-07-0
E3 = TESTPOINT_.219_MILL-MAX_2501: TEST POINT,TURRET,0.094" MTG. HOLE,PCB 0.062" THK; CLASS: IO; Inventory Qty: 609555; Label1: GND; Label2: 14V MAX; Manufacturer: MILL-MAX; Manufacturer PN: 2501-2-00-80-00-00-07-0; PART_NUMBER: 260-0003; Part Number: MILL-MAX 2501-2-00-80-00-00-07-0
E4 = TESTPOINT_.219_MILL-MAX_2501: TEST POINT,TURRET,0.094" MTG. HOLE,PCB 0.062" THK; CLASS: IO; Inventory Qty: 609555; Label1: PLLIN; Label2: 14V MAX; Manufacturer: MILL-MAX; Manufacturer PN: 2501-2-00-80-00-00-07-0; PART_NUMBER: 260-0003; Part Number: MILL-MAX 2501-2-00-80-00-00-07-0
E5 = TESTPOINT_.219_MILL-MAX_2501: TEST POINT,TURRET,0.094" MTG. HOLE,PCB 0.062" THK; CLASS: IO; Inventory Qty: 609555; Label1: CLKOUT; Label2: 14V MAX; Manufacturer: MILL-MAX; Manufacturer PN: 2501-2-00-80-00-00-07-0; PART_NUMBER: 260-0003; Part Number: MILL-MAX 2501-2-00-80-00-00-07-0
E6 = TESTPOINT_.219_MILL-MAX_2501: TEST POINT,TURRET,0.094" MTG. HOLE,PCB 0.062" THK; CLASS: IO; Inventory Qty: 609555; Label1: RUN; Label2: 14V MAX; Manufacturer: MILL-MAX; Manufacturer PN: 2501-2-00-80-00-00-07-0; PART_NUMBER: 260-0003; Part Number: MILL-MAX 2501-2-00-80-00-00-07-0
E7 = TESTPOINT_.219_MILL-MAX_2501: TEST POINT,TURRET,0.094" MTG. HOLE,PCB 0.062" THK; CLASS: IO; Inventory Qty: 609555; Label1: FAULT; Label2: 14V MAX; Manufacturer: MILL-MAX; Manufacturer PN: 2501-2-00-80-00-00-07-0; PART_NUMBER: 260-0003; Part Number: MILL-MAX 2501-2-00-80-00-00-07-0
E8 = TESTPOINT_.219_MILL-MAX_2501: TEST POINT,TURRET,0.094" MTG. HOLE,PCB 0.062" THK; CLASS: IO; Inventory Qty: 609555; Label1: VO_SNS+; Label2: 14V MAX; Manufacturer: MILL-MAX; Manufacturer PN: 2501-2-00-80-00-00-07-0; PART_NUMBER: 260-0003; Part Number: MILL-MAX 2501-2-00-80-00-00-07-0
E9 = TESTPOINT_.219_MILL-MAX_2501: TEST POINT,TURRET,0.094" MTG. HOLE,PCB 0.062" THK; CLASS: IO; Inventory Qty: 609555; Label1: VO_SNS-; Label2: 14V MAX; Manufacturer: MILL-MAX; Manufacturer PN: 2501-2-00-80-00-00-07-0; PART_NUMBER: 260-0003; Part Number: MILL-MAX 2501-2-00-80-00-00-07-0
E10 = TESTPOINT_.219_MILL-MAX_2501: TEST POINT,TURRET,0.094" MTG. HOLE,PCB 0.062" THK; CLASS: IO; Inventory Qty: 609555; Label1: PGOOD; Label2: 14V MAX; Manufacturer: MILL-MAX; Manufacturer PN: 2501-2-00-80-00-00-07-0; PART_NUMBER: 260-0003; Part Number: MILL-MAX 2501-2-00-80-00-00-07-0
E11 = TESTPOINT_.219_MILL-MAX_2501: TEST POINT,TURRET,0.094" MTG. HOLE,PCB 0.062" THK; CLASS: IO; Inventory Qty: 609555; Label1: EXT_REF; Label2: 14V MAX; Manufacturer: MILL-MAX; Manufacturer PN: 2501-2-00-80-00-00-07-0; PART_NUMBER: 260-0003; Part Number: MILL-MAX 2501-2-00-80-00-00-07-0
E12 = TESTPOINT_.219_MILL-MAX_2501: TEST POINT,TURRET,0.094" MTG. HOLE,PCB 0.062" THK; CLASS: IO; Inventory Qty: 609555; Label1: SGND; Label2: 14V MAX; Manufacturer: MILL-MAX; Manufacturer PN: 2501-2-00-80-00-00-07-0; PART_NUMBER: 260-0003; Part Number: MILL-MAX 2501-2-00-80-00-00-07-0
E15 = TESTPOINT_.219_MILL-MAX_2501: TEST POINT,TURRET,0.094" MTG. HOLE,PCB 0.062" THK; CLASS: IO; Inventory Qty: 609555; Label1: TEMP1+; Label2: 14V MAX; Manufacturer: MILL-MAX; Manufacturer PN: 2501-2-00-80-00-00-07-0; PART_NUMBER: 260-0003; Part Number: MILL-MAX 2501-2-00-80-00-00-07-0
E16 = TESTPOINT_.219_MILL-MAX_2501: TEST POINT,TURRET,0.094" MTG. HOLE,PCB 0.062" THK; CLASS: IO; Inventory Qty: 609555; Label1: TEMP1-; Label2: 14V MAX; Manufacturer: MILL-MAX; Manufacturer PN: 2501-2-00-80-00-00-07-0; PART_NUMBER: 260-0003; Part Number: MILL-MAX 2501-2-00-80-00-00-07-0
J1 = PEM-KFH: EVAL BOARD STUD HARDWARE SET, #10-32; 11th Part Field: VIN; 9th Part Field: 30V ~ 60V; CLASS: DISCRETE; Comments: CONSISTS OF QTY(1) STUD, 769-0012; QTY(1) RING LUG, 769-0013;QTY(2) HEX NUT,BRASS,761-0013; QTY(1) WASHER,#10 LOCK, 762-0021; Manufacturer: ANALOG DEVICES; Manufacturer PN: 720-0010; PART_NUMBER: 720-0010
J2 J4 = PEM-KFH: EVAL BOARD STUD HARDWARE SET, #10-32; 11th Part Field: GND; 9th Part Field: 12V / UP TO 100A; CLASS: DISCRETE; Comments: CONSISTS OF QTY(1) STUD, 769-0012; QTY(1) RING LUG, 769-0013;QTY(2) HEX NUT,BRASS,761-0013; QTY(1) WASHER,#10 LOCK, 762-0021; Manufacturer: ANALOG DEVICES; Manufacturer PN: 720-0010; PART_NUMBER: 720-0010
J3 = PEM-KFH: EVAL BOARD STUD HARDWARE SET, #10-32; 11th Part Field: VOUT; 9th Part Field: 12V / UP TO 100A; CLASS: DISCRETE; Comments: CONSISTS OF QTY(1) STUD, 769-0012; QTY(1) RING LUG, 769-0013;QTY(2) HEX NUT,BRASS,761-0013; QTY(1) WASHER,#10 LOCK, 762-0021; Manufacturer: ANALOG DEVICES; Manufacturer PN: 720-0010; PART_NUMBER: 720-0010
JP1 = HDR1X4_ALT1: CONN.,HDR,MALE,1x4,2mm,VERT,ST,THT; 10th Part Field: BM; 12th Part Field: CCM; 13tht Part Field: MODE; 9th Part Field: PS; CLASS: IO; Inventory Qty: 10951; Manufacturer: WURTH ELEKTRONIK; Manufacturer PN: 62000411121; PART_NUMBER: 250-0563
R1 R26 R42 R52 = RES: RES.,0 OHM,1/10W,0603,AEC-Q200; CLASS: DISCRETE; FPLIST: CR0603N,CR0603L,CR0603M; Inventory Qty: 716568; Manufacturer: VISHAY; Manufacturer PN: CRCW06030000Z0EA; PART_NUMBER: 100-0009; Package Size: 0603; Part Number: VISHAY CRCW06030000Z0EA; Rated Power: 1/10W
R2 R22 = RES: RES.,20k OHMS,5%,1/10W,0603,AEC-Q200; CLASS: DISCRETE; FPLIST: CR0603N,CR0603L,CR0603M; Inventory Qty: 36533; Manufacturer: NIC; Manufacturer PN: NRC06J203TRF; PART_NUMBER: 100-0160; Package Size: 0603; Part Number: VISHAY CRCW060320K0JNEA; Rated Power: 1/10W; Temperature Coefficient: 200ppm/C; Tolerance: 5%
R3 R9 R12 R16 R18 R30 R36 R37 R40 R41 R43 R44 R48 R50 R51 R53 R58 R60 R61 R65 = RES: RES.,0 OHM,1/10W,0603,AEC-Q200; CLASS: DISCRETE; FPLIST: CR0603N,CR0603L,CR0603M; Inventory Qty: 716568; Manufacturer: VISHAY; Manufacturer PN: CRCW06030000Z0EA; PART_NUMBER: 100-0009; Package Size: 0603; Rated Power: 1/10W
R4 = RES: RES.,1M OHM,1%,1/8W,0805,AEC-Q200; CLASS: DISCRETE; FPLIST: CR0805N,CR0805L,CR0805M; Inventory Qty: 23820; Manufacturer: PANASONIC; Manufacturer PN: ERJ6ENF1004V; PART_NUMBER: 100-2835; Package Size: 0805; Part Number: VISHAY CRCW08051M00FKEA; Rated Power: 1/8W; Temperature Coefficient: +/-100ppm; Tolerance: 1%
R5 = RES: RES.,46.4k OHMS,1%,1/10W,0603; CLASS: DISCRETE; FPLIST: CR0603N,CR0603L,CR0603M; Inventory Qty: 26316; Manufacturer: NIC; Manufacturer PN: NRC06F4642TRF; PART_NUMBER: 100-2595; Package Size: 0603; Rated Power: 1/10W; Temperature Coefficient: 100ppm/C; Tolerance: 1%
R6 R13 = RES: RES.,10k OHMS,1%,1/10W,0603,AEC-Q200; CLASS: DISCRETE; FPLIST: CR0603N,CR0603L,CR0603M; Inventory Qty: 161332; Manufacturer: VISHAY; Manufacturer PN: CRCW060310K0FKEA; PART_NUMBER: 100-2012; Package Size: 0603; Part Number: VISHAY CRCW060310K0FKEA; Rated Power: 1/10W; Temperature Coefficient: +/-100ppm/C; Tolerance: 1%
R7 R38 R45 R55 = RES: RES.,100k OHMS,1%,1/10W,0603,AEC-Q200; CLASS: DISCRETE; FPLIST: CR0603N,CR0603L,CR0603M; Inventory Qty: 186117; Manufacturer: VISHAY; Manufacturer PN: CRCW0603100KFKEA; PART_NUMBER: 100-0343; Package Size: 0603; Part Number: VISHAY CRCW0603100KFKEA; Rated Power: 1/10W; Temperature Coefficient: +/-100ppm; Tolerance: 1%
R8 = RES: RES., OPTION, 0805; CLASS: DISCRETE; FPLIST: CR0805N,CR0805L,CR0805M; PART_NUMBER: 100-2558; Package Size: 0805
R10 R39 R46 R56 = RES: RES.,49.9k OHMS,1%,1/10W,0603; CLASS: DISCRETE; Inventory Qty: 100527; Manufacturer: NIC; Manufacturer PN: NRC06F4992TRF; PART_NUMBER: 100-0303; Package Size: 0603; Rated Power: 1/10W; Temperature Coefficient: 100ppm/C; Tolerance: 1%
R14 R15 = RES: RES., OPTION, 0603; CLASS: DISCRETE; FPLIST: CR0603N,CR0603L,CR0603M; PART_NUMBER: 100-2374; Package Size: 0603
R17 R20 R29 R47 R57 R63 R64 = RES: RES., OPTION, 0603; CLASS: DISCRETE; FPLIST: CR0603N,CR0603L,CR0603M; PART_NUMBER: 100-2374; Package Size: 0603; Part Number: OPTION
R19 = RES: RES.,1.07k OHMS,1%,1/10W,0603,AEC-Q200; CLASS: DISCRETE; FPLIST: CR0603N,CR0603L,CR0603M; Inventory Qty: 23664; Manufacturer: PANASONIC; Manufacturer PN: ERJ3EKF1071V; PART_NUMBER: 100-0403; Package Size: 0603; Part Number: VISHAY CRCW06034K32FKEA; Rated Power: 1/10W; Temperature Coefficient: 100ppm; Tolerance: 1%
R62 = RES: RES.,50 OHMS,0.1%,1/8W,0603; CLASS: DISCRETE; FPLIST: CR0603N,CR0603L,CR0603M; Inventory Qty: 525; Manufacturer: VISHAY; Manufacturer PN: FC0603E50R0BST1; PART_NUMBER: 100-2865; Package Size: 0603; Part Number: OPTION; Rated Power: 1/8W; Temperature Coefficient: +/-25PPM; Tolerance: 0.1%
RN1-RN4 = THERMISTOR-GENERAL: THERMISTOR, OPTION, 0603; CLASS: DISCRETE; FPLIST: CR0603N,CR0603L,CR0603M; PART_NUMBER: 122-0005; Package Size: 0603
SW1 = SW-DPDT-JS202011CQN_ALT4: SWITCH,SLIDE,DPDT,0.3A,6VDC,PTH; CLASS: DISCRETE; Inventory Qty: 32221; Manufacturer: C&K; Manufacturer PN: JS202011CQN; PART_NUMBER: 430-0039
TP1-TP4 = PAD_2: Component: tp; Label: <Label>
U1-U4 = LTM4660-BGA: IC,HYBRID STEP-DOWN NON-ISOLATED uMODULE BUS CONVERTER,BGA; CLASS: IC; Inventory Qty: 0; LABEL: LTM4660IY; Manufacturer: ANALOG DEVICES; Manufacturer PN: LTM4660IY#PBF; PART_NUMBER: LTM4660IY#PBF; Package Type: BGA
XJP1 XJP2 = SHUNT_2MM: CONN.,SHUNT,FEMALE,2 POS,2mm; CLASS: IO; Inventory Qty: 67555; Manufacturer: Wurth Elektronik; Manufacturer PN: 60800213421; PART_NUMBER: 250-0485
E17 = TESTPOINT_.219_MILL-MAX_2501: TEST POINT,TURRET,0.094" MTG. HOLE,PCB 0.062" THK; CLASS: IO; Inventory Qty: 609555; Label1: TEMP2+; Label2: 14V MAX; Manufacturer: MILL-MAX; Manufacturer PN: 2501-2-00-80-00-00-07-0; PART_NUMBER: 260-0003; Part Number: MILL-MAX 2501-2-00-80-00-00-07-0
E18 = TESTPOINT_.219_MILL-MAX_2501: TEST POINT,TURRET,0.094" MTG. HOLE,PCB 0.062" THK; CLASS: IO; Inventory Qty: 609555; Label1: TEMP2-; Label2: 14V MAX; Manufacturer: MILL-MAX; Manufacturer PN: 2501-2-00-80-00-00-07-0; PART_NUMBER: 260-0003; Part Number: MILL-MAX 2501-2-00-80-00-00-07-0
E19 = TESTPOINT_.219_MILL-MAX_2501: TEST POINT,TURRET,0.094" MTG. HOLE,PCB 0.062" THK; CLASS: IO; Inventory Qty: 609555; Label1: TEMP3+; Label2: 14V MAX; Manufacturer: MILL-MAX; Manufacturer PN: 2501-2-00-80-00-00-07-0; PART_NUMBER: 260-0003; Part Number: MILL-MAX 2501-2-00-80-00-00-07-0
E20 = TESTPOINT_.219_MILL-MAX_2501: TEST POINT,TURRET,0.094" MTG. HOLE,PCB 0.062" THK; CLASS: IO; Inventory Qty: 609555; Label1: TEMP3-; Label2: 14V MAX; Manufacturer: MILL-MAX; Manufacturer PN: 2501-2-00-80-00-00-07-0; PART_NUMBER: 260-0003; Part Number: MILL-MAX 2501-2-00-80-00-00-07-0
E21 = TESTPOINT_.219_MILL-MAX_2501: TEST POINT,TURRET,0.094" MTG. HOLE,PCB 0.062" THK; CLASS: IO; Inventory Qty: 609555; Label1: TEMP4+; Label2: 14V MAX; Manufacturer: MILL-MAX; Manufacturer PN: 2501-2-00-80-00-00-07-0; PART_NUMBER: 260-0003; Part Number: MILL-MAX 2501-2-00-80-00-00-07-0
E22 = TESTPOINT_.219_MILL-MAX_2501: TEST POINT,TURRET,0.094" MTG. HOLE,PCB 0.062" THK; CLASS: IO; Inventory Qty: 609555; Label1: TEMP4-; Label2: 14V MAX; Manufacturer: MILL-MAX; Manufacturer PN: 2501-2-00-80-00-00-07-0; PART_NUMBER: 260-0003; Part Number: MILL-MAX 2501-2-00-80-00-00-07-0
E23 = TESTPOINT_.219_MILL-MAX_2501: TEST POINT,TURRET,0.094" MTG. HOLE,PCB 0.062" THK; CLASS: IO; Inventory Qty: 609555; Label1: CLKOUT_U4; Label2: 14V MAX; Manufacturer: MILL-MAX; Manufacturer PN: 2501-2-00-80-00-00-07-0; PART_NUMBER: 260-0003; Part Number: MILL-MAX 2501-2-00-80-00-00-07-0
C49 C50 = CAP: CAP.,22uF,X5R,25V,10%,1210; CLASS: DISCRETE; Dielectric Type: X5R; FPLIST: CC1210N,CC1210L,CC1210M; Inventory Qty: 25866; Manufacturer: KEMET; Manufacturer PN: C1210C226K3PACTU; PART_NUMBER: 150-3033; Package Size: 1210; Package Type: SMD; Part Number: MURATA GRM32ER61E226KE15L; Rated Voltage: 25V; Tolerance: 10%
C51 = CAP: CAP.,0.047uF,X7R,25V,10%,0603; CLASS: DISCRETE; Dielectric Type: X7R; FPLIST: CC0603N,CC0603L,CC0603M; Inventory Qty: 35615; Manufacturer: MURATA; Manufacturer PN: GRM188R71E473KA01D; PART_NUMBER: 150-0063; Package Size: 0603; Part Number: MURATA GRM188R71E473KA01D; Rated Voltage: 25V; Tolerance: 10%
C52 = CAP: CAP.,220pF,C0G,50V,5%,0603; CLASS: DISCRETE; Dielectric Type: C0G; FPLIST: CC0603N,CC0603L,CC0603M; Inventory Qty: 19803; Manufacturer: AVX; Manufacturer PN: 06035A221JAT2A; PART_NUMBER: 150-0031; Package Size: 0603; Part Number: MURATA GRM1885C1H221JA01J; Rated Voltage: 50V; Tolerance: 5%
C53 = CAP: CAP.,1uF,X7R,25V,10%,0603,AEC-Q200; CLASS: DISCRETE; Dielectric Type: X7R; FPLIST: CC0603N,CC0603L,CC0603M; Inventory Qty: 30139; Manufacturer: MURATA; Manufacturer PN: GCM188R71E105KA64D; PART_NUMBER: 150-0291; Package Size: 0603; Part Number: MURATA GRM188R61E105KA12D; Rated Voltage: 25V; Tolerance: 10%
E13 = TESTPOINT_.219_MILL-MAX_2501: TEST POINT,TURRET,0.094" MTG. HOLE,PCB 0.062" THK; 1st Part Field: IO_CLK; CLASS: IO; FPLIST: MILLMAX2501,MILLMAX2501_ALT1; Inventory Qty: 609555; Manufacturer: MILL-MAX; Manufacturer PN: 2501-2-00-80-00-00-07-0; PART_NUMBER: 260-0003; Part Number: MILL-MAX 2501-2-00-80-00-00-07-0
E14 = TESTPOINT_.219_MILL-MAX_2501: TEST POINT,TURRET,0.094" MTG. HOLE,PCB 0.062" THK; 1st Part Field: GND; CLASS: IO; FPLIST: MILLMAX2501,MILLMAX2501_ALT1; Inventory Qty: 609555; Manufacturer: MILL-MAX; Manufacturer PN: 2501-2-00-80-00-00-07-0; PART_NUMBER: 260-0003; Part Number: MILL-MAX 2501-2-00-80-00-00-07-0
J5 = BNC_50_OHM_112404_B: CONN.,RF,BNC,RCPT,JACK,5-PIN,ST,THT,50 OHMS; 1st Part Field: VOUT; CLASS: IO; Inventory Qty: 80261; Manufacturer: AMPHENOL RF; Manufacturer PN: 112404; PART_NUMBER: 250-0427; Part Number: CONNEX 112404
J6 = BNC_50_OHM_112404_B: CONN.,RF,BNC,RCPT,JACK,5-PIN,ST,THT,50 OHMS; 1st Part Field: IOSTEP; CLASS: IO; Inventory Qty: 80261; Manufacturer: AMPHENOL RF; Manufacturer PN: 112404; PART_NUMBER: 250-0427; Part Number: CONNEX 112404
JP2 = 1X3_A: CONN.,HDR,MALE,1x3,2mm,VERT,ST,THT,NO SUBS. ALLOWED; 11th Part Field: OFF; 12th Part Field: BIAS; 9th Part Field: ON; CLASS: IO; Inventory Qty: 24006; Manufacturer: Wurth Elektronik; Manufacturer PN: 62000311121; PART_NUMBER: 250-0639
L3 = IND: IND.,68uH,PWR, SHIELDED,20%,0.74A,0.42 OHM,2424, LPS6225; 1st Part Field: LPS6225-683MRB; CLASS: DISCRETE; Inventory Qty: 1313; Manufacturer: Coilcraft; Manufacturer PN: LPS6225-683MRB; PART_NUMBER: 200-0477; Package Size: 2424, LPS6225; Part Number: COILCRAFT LPS6225-683MRB; Tolerance: 20%
Q11 Q12 = 3P_N-CH_TYPE2A: XSTR.,MOSFET,N-CH,40V,14A,DPAK (TO-252); CLASS: DISCRETE; FPLIST: TO-252-3N,TO-252-3L,TO-252-3M; Inventory Qty: 40309; Manufacturer: VISHAY; Manufacturer PN: SUD50N04-8M8P-4GE3; PART_NUMBER: 240-0021; Package Type: DPAK (TO-252); Part Number: VISHAY SILICONIX SUD50N04-8M8P-4GE3; Rated Voltage: 40V
R21 = RES: RES.,182k OHMS,1%,1/10W,0603,AEC-Q200; CLASS: DISCRETE; FPLIST: CR0603N,CR0603L,CR0603M; Inventory Qty: 53751; Manufacturer: PANASONIC; Manufacturer PN: ERJ3EKF1823V; PART_NUMBER: 100-2770; Package Size: 0603; Part Number: PANASONIC ERJ3EKF1823V; Rated Power: 1/10W; Temperature Coefficient: 100ppm/C; Tolerance: 1%
R23 = RES: RES.,80.6k OHMS,1%,1/10W,0603; CLASS: DISCRETE; FPLIST: CR0603N,CR0603L,CR0603M; Inventory Qty: 41958; Manufacturer: VISHAY; Manufacturer PN: CRCW060380K6FKEA; PART_NUMBER: 100-2503; Package Size: 0603; Part Number: VISHAY CRCW060380K6FKEA; Rated Power: 1/10W; Temperature Coefficient: 100ppm/C; Tolerance: 1%
R24 = RES: RES.,10k OHMS,1%,1/10W,0603,AEC-Q200; CLASS: DISCRETE; FPLIST: CR0603N,CR0603L,CR0603M; Inventory Qty: 161332; Manufacturer: VISHAY; Manufacturer PN: CRCW060310K0FKEA; PART_NUMBER: 100-2012; Package Size: 0603; Rated Power: 1/10W; Temperature Coefficient: +/-100ppm/C; Tolerance: 1%
R25 = RES: RES.,0.1 OHM,1%,1W,2010,WSL-18 Series, SENSE, AEC-Q200; CLASS: DISCRETE; Inventory Qty: 15978; Manufacturer: VISHAY; Manufacturer PN: WSL2010R1000FEA18; PART_NUMBER: 100-0994; Package Size: 2010; Rated Power: 1W; Temperature Coefficient: 75ppm; Tolerance: 1%
U5 = LTC3630-MSE: IC,Synchr. Step-Down Converter,MSOP-16 (MSE),76V, 500mA; CLASS: IC; Inventory Qty: 680; Manufacturer: LINEAR TECH.; Manufacturer PN: LTC3630AEMSE#PBF; PART_NUMBER: LTC3630AEMSE#PBF; Package Type: MSOP-16 (MSE)
LB1 = BLANK_LABEL: LABEL SPEC, DEMO BOARD SERIAL NUMBER; Inventory Qty: 0; Manufacturer: BRADY; Manufacturer PN: THT-96-717-10; PART_NUMBER: 895-0154
MH1-MH10 = MP-PINNED: STANDOFF,NYLON,SNAP-ON,0.625 (5/8"),15.9mm; CLASS: DISCRETE; Inventory Qty: 162629; Manufacturer: KEYSTONE; Manufacturer PN: 8834; PART_NUMBER: 763-0013; Part Number: KEYSTONE_8833
PCB1 = BLANK_PCB_PART: BOM Notes: REV02; CLASS: DISCRETE; Inventory Qty: 0; Manufacturer: PHASE 3; Manufacturer PN: 600-DC2959A; PART_NUMBER: 600-DC2959A
STNCL1 = BLANK_STENCIL_PART: BOM Notes: REV02; CLASS: DISCRETE; Inventory Qty: 0; Manufacturer: ANALOG DEVICES; Manufacturer PN: 830-DC2959A; PART_NUMBER: 830-DC2959A

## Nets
+8V: C48.1 C49.1 C50.1 L3.2 R20.1 R21.2
GND: C1.2 C2.2 C3.2 C4.2 C5.2 C14.2 C15.2 C22.2 C23.2 C24.2 C25.2 C26.2 C27.2 C28.2 C29.2 C30.2 C31.2 C32.2 C33.2 C34.2 C35.1 C38.2 C39.2 C40.2 C41.2 C42.2 C46.2 C47.2 C49.2 C50.2 C51.2 C52.2 C53.1 C57.2 C58.2 C59.2 C60.2 C61.2 C62.2 C63.2 C77.2 C78.2 C79.2 C80.2 C81.2 C82.2 C83.2 C84.2 C85.2 C86.2 C87.2 C88.2 C89.2 C91.2 C92.2 C93.2 C94.2 C95.2 C97.2 C98.2 C99.2 C100.2 C101.2 C102.2 C103.2 C118.2 C119.2 C120.2 C121.2 C122.2 C123.2 C124.2 C125.2 C126.2 C127.2 C128.2 C129.2 C130.2 C132.2 C133.2 C134.2 C135.2 C136.2 C138.2 C139.2 C140.2 C141.2 C142.2 C143.2 C144.2 C159.2 C160.2 C161.2 C162.2 C163.2 C164.2 C165.2 C166.2 C167.2 C168.2 C169.2 C170.2 C171.2 C173.2 C174.2 C175.2 C176.2 C183.2 C184.2 C185.2 E3.1 E9.1 E14.1 J2.1 J4.1 J5.2 J5.3 J5.4 J5.5 J6.2 J6.3 J6.4 J6.5 JP2.3 R5.2 R22.1 R23.2 R24.2 R25.2 SW1.3 U1.A12(GND) U1.B12(GND) U1.C12(GND) U1.D9(GND) U1.D10(GND) U1.D11(GND) U1.D12(GND) U1.E9(GND) U1.E10(GND) U1.E11(GND) U1.E12(GND) U1.F9(GND) U1.F10(GND) U1.F11(GND) U1.F12(GND) U1.G9(GND) U1.H9(GND) U1.J1(GND) U1.J2(GND) U1.K1(GND) U1.K2(GND) U1.L1(GND) U1.L2(GND) U1.M1(GND) U2.A12(GND) U2.B12(GND) U2.C12(GND) U2.D9(GND) U2.D10(GND) U2.D11(GND) U2.D12(GND) U2.E9(GND) U2.E10(GND) U2.E11(GND) U2.E12(GND) U2.F9(GND) U2.F10(GND) U2.F11(GND) U2.F12(GND) U2.G9(GND) U2.H9(GND) U2.J1(GND) U2.J2(GND) U2.K1(GND) U2.K2(GND) U2.L1(GND) U2.L2(GND) U2.M1(GND) U3.A12(GND) U3.B12(GND) U3.C12(GND) U3.D9(GND) U3.D10(GND) U3.D11(GND) U3.D12(GND) U3.E9(GND) U3.E10(GND) U3.E11(GND) U3.E12(GND) U3.F9(GND) U3.F10(GND) U3.F11(GND) U3.F12(GND) U3.G9(GND) U3.H9(GND) U3.J1(GND) U3.J2(GND) U3.K1(GND) U3.K2(GND) U3.L1(GND) U3.L2(GND) U3.M1(GND) U4.A12(GND) U4.B12(GND) U4.C12(GND) U4.D9(GND) U4.D10(GND) U4.D11(GND) U4.D12(GND) U4.E9(GND) U4.E10(GND) U4.E11(GND) U4.E12(GND) U4.F9(GND) U4.F10(GND) U4.F11(GND) U4.F12(GND) U4.G9(GND) U4.H9(GND) U4.J1(GND) U4.J2(GND) U4.K1(GND) U4.K2(GND) U4.L1(GND) U4.L2(GND) U4.M1(GND) U5.6(VPRG2) U5.7(VPRG1) U5.8(GND) U5.14(GND) U5.16(GND) U5.17(GND)
GND_POWER: C21.1 C36.1 C37.1 C43.1 C45.1 C54.1 C90.1 C96.1 C131.1 C137.1 C172.1 C178.1 C179.1 C180.1 C181.1 C182.1 E12.1 E16.1 E18.1 E20.1 E22.1 JP1.4 R7.2 R10.2 R14.2 R18.2 R19.2 R30.1 R38.2 R39.2 R45.2 R46.2 R50.1 R55.2 R56.2 R60.1 R64.2 RN1.1 RN2.1 RN3.1 RN4.1 U1.K9(TEMP-) U1.L4(SGND) U1.L12(SGND) U1.M12(SGND) U2.K9(TEMP-) U2.L4(SGND) U2.L12(SGND) U2.M12(SGND) U3.K9(TEMP-) U3.L4(SGND) U3.L12(SGND) U3.M12(SGND) U4.K9(TEMP-) U4.L4(SGND) U4.L12(SGND) U4.M12(SGND)
VIN: C1.1 C2.1 C3.1 C4.1 C5.1 C14.1 C15.1 C46.1 C47.1 C57.1 C58.1 C59.1 C60.1 C61.1 C62.1 C63.1 C97.1 C98.1 C99.1 C100.1 C101.1 C102.1 C103.1 C138.1 C139.1 C140.1 C141.1 C142.1 C143.1 C144.1 E2.1 J1.1 R1.2 R4.1 R8.1 R26.2 R42.2 R52.2 U1.A5(VIN) U1.B5(VIN) U1.C5(VIN) U1.D5(VIN) U1.E5(VIN) U2.A5(VIN) U2.B5(VIN) U2.C5(VIN) U2.D5(VIN) U2.E5(VIN) U3.A5(VIN) U3.B5(VIN) U3.C5(VIN) U3.D5(VIN) U3.E5(VIN) U4.A5(VIN) U4.B5(VIN) U4.C5(VIN) U4.D5(VIN) U4.E5(VIN) U5.3(VIN)
CLKOUT_U1: E5.1 R36.1 U1.M4(CLKOUT)
CLKOUT_U2: R37.1 R43.1
CLKOUT_U3: R44.1 R53.1
COMP: C54.2 C96.2 C137.2 C178.2 R15.2 R16.2 R41.2 R51.2 R61.2 U1.M10(COMPa) U2.M10(COMPa) U3.M10(COMPa) U4.M10(COMPa)
EXT_REF: C37.2 E11.1 R8.2 R9.1 R14.1 U1.M9(EXT_REF) U2.M9(EXT_REF) U3.M9(EXT_REF) U4.M9(EXT_REF)
EXTVCC: R3.2 R20.2 U1.K10(EXTVCC) U2.K10(EXTVCC) U3.K10(EXTVCC) U4.K10(EXTVCC)
FAULT: E7.1 R6.2 U1.J3(/FAULT) U2.J3(/FAULT) U3.J3(/FAULT) U4.J3(/FAULT)
INTVCC: R2.2 R6.1 R9.2 R13.1 R17.1 U1.J4(INTVCC)
INTVCC2: R29.1 U2.J4(INTVCC)
INTVCC3: R47.1 U3.J4(INTVCC)
INTVCC4: R57.1 U4.J4(INTVCC)
PGOOD: E10.1 R13.2 U1.M2(PGOOD) U2.M2(PGOOD) U3.M2(PGOOD) U4.M2(PGOOD)
RUN: C35.2 E6.1 R4.2 R5.1 SW1.1 SW1.2 U1.L3(RUN) U2.L3(RUN) U3.L3(RUN) U4.L3(RUN)
TRACK: C36.2 U1.L9(TK/SS) U2.L9(TK/SS) U3.L9(TK/SS) U4.L9(TK/SS)
VFB: C44.1 C45.2 R19.1 R63.2 R64.1 U1.K12(VFB) U2.K12(VFB) U3.K12(VFB) U4.K12(VFB)
VOUT: C38.1 C39.1 C40.1 C41.1 C42.1 C44.2 C53.2 C91.1 C92.1 C93.1 C94.1 C95.1 C132.1 C133.1 C134.1 C135.1 C136.1 C173.1 C174.1 C175.1 C176.1 C177.1 C183.1 C184.1 C185.1 C186.1 E8.1 J3.1 J5.1 Q11.2(D) Q12.2(D) R3.1 R62.1 U1.A1(VOUT) U1.A2(VOUT) U1.A3(VOUT) U1.B1(VOUT) U1.B2(VOUT) U1.B3(VOUT) U1.C1(VOUT) U1.C2(VOUT) U1.C3(VOUT) U1.D1(VOUT) U1.D2(VOUT) U1.D3(VOUT) U1.E3(VOUT) U1.F3(VOUT) U1.G3(VOUT) U1.H3(VOUT) U2.A1(VOUT) U2.A2(VOUT) U2.A3(VOUT) U2.B1(VOUT) U2.B2(VOUT) U2.B3(VOUT) U2.C1(VOUT) U2.C2(VOUT) U2.C3(VOUT) U2.D1(VOUT) U2.D2(VOUT) U2.D3(VOUT) U2.E3(VOUT) U2.F3(VOUT) U2.G3(VOUT) U2.H3(VOUT) U3.A1(VOUT) U3.A2(VOUT) U3.A3(VOUT) U3.B1(VOUT) U3.B2(VOUT) U3.B3(VOUT) U3.C1(VOUT) U3.C2(VOUT) U3.C3(VOUT) U3.D1(VOUT) U3.D2(VOUT) U3.D3(VOUT) U3.E3(VOUT) U3.F3(VOUT) U3.G3(VOUT) U3.H3(VOUT) U4.A1(VOUT) U4.A2(VOUT) U4.A3(VOUT) U4.B1(VOUT) U4.B2(VOUT) U4.B3(VOUT) U4.C1(VOUT) U4.C2(VOUT) U4.C3(VOUT) U4.D1(VOUT) U4.D2(VOUT) U4.D3(VOUT) U4.E3(VOUT) U4.F3(VOUT) U4.G3(VOUT) U4.H3(VOUT)
N139306: C6.2 C7.2 C8.2 C9.2 C10.2 C11.2 C12.2 C13.2 C16.2 C17.2 C18.2 C19.2 C20.2 U1.A8(C-) U1.A9(C-) U1.A10(C-) U1.A11(C-) U1.B8(C-) U1.B9(C-) U1.B10(C-) U1.B11(C-) U1.C8(C-) U1.C9(C-) U1.C10(C-) U1.C11(C-) U1.D8(C-) U1.E8(C-) U1.F8(C-) U1.G8(C-) U1.H8(C-) U1.J8(C-) U1.K8(C-) U1.L8(C-) U1.M8(C-)
N139310: C6.1 C7.1 C8.1 C9.1 C10.1 C11.1 C12.1 C13.1 C16.1 C17.1 C18.1 C19.1 C20.1 U1.A6(C+) U1.B6(C+) U1.C6(C+) U1.D6(C+) U1.E6(C+) U1.F6(C+) U1.G5(C+) U1.G6(C+) U1.H5(C+) U1.H6(C+) U1.J6(C+) U1.K6(C+) U1.L6(C+) U1.M6(C+)
N140832: C22.1 C23.1 C24.1 C25.1 C26.1 C27.1 C28.1 C29.1 C30.1 C31.1 C32.1 C33.1 C34.1 R12.2 U1.E1(MID) U1.E2(MID) U1.F1(MID) U1.F2(MID) U1.G1(MID) U1.G2(MID) U1.G10(MID) U1.G11(MID) U1.G12(MID) U1.H1(MID) U1.H10(MID) U1.H11(MID) U1.H12(MID) U1.J10(MID) U1.J11(MID) U1.J12(MID)
N141583: R12.1 U1.H2(MID_SENSE)
N144217: R1.1 U1.F5(VIN_SNS)
N146535: E4.1 JP1.2 JP1.3 U1.M3(MODE_PLLIN)
N146873: JP1.1 R2.1
N146893: C21.2 U1.K3(TIMER)
N149369: R16.1 U1.L10(COMPb)
N149924: R10.1 U1.M11(FREQ)
N150764: R17.2 R18.1 RN1.2 U1.K11(TEMP)
N156581: E13.1 Q11.1(G) Q12.1(G) R24.1
N156601: J6.1 Q11.3(S) Q12.3(S) R25.1
N157579: C52.1 R23.1 U5.11(ISET)
N157583: C51.1 U5.10(SS)
N157591: C48.2 R21.1 R22.2 U5.9(VFB)
N157835: L3.1 U5.1(SW)
N165559: TP1.1(TP) U1.K4(TEST)
N178912: JP2.2 U5.5(RUN)
N16663186: R7.1 U1.L11(HYS_PRGM)
N16683043: C64.1 C65.1 C66.1 C67.1 C68.1 C69.1 C70.1 C71.1 C72.1 C73.1 C74.1 C75.1 C76.1 U2.A6(C+) U2.B6(C+) U2.C6(C+) U2.D6(C+) U2.E6(C+) U2.F6(C+) U2.G5(C+) U2.G6(C+) U2.H5(C+) U2.H6(C+) U2.J6(C+) U2.K6(C+) U2.L6(C+) U2.M6(C+)
N16683087: R26.1 U2.F5(VIN_SNS)
N16683639: C64.2 C65.2 C66.2 C67.2 C68.2 C69.2 C70.2 C71.2 C72.2 C73.2 C74.2 C75.2 C76.2 U2.A8(C-) U2.A9(C-) U2.A10(C-) U2.A11(C-) U2.B8(C-) U2.B9(C-) U2.B10(C-) U2.B11(C-) U2.C8(C-) U2.C9(C-) U2.C10(C-) U2.C11(C-) U2.D8(C-) U2.E8(C-) U2.F8(C-) U2.G8(C-) U2.H8(C-) U2.J8(C-) U2.K8(C-) U2.L8(C-) U2.M8(C-)
N16683915: R36.2 U2.M3(MODE_PLLIN)
N16683951: R37.2 U2.M4(CLKOUT)
N16683971: C77.1 C78.1 C79.1 C80.1 C81.1 C82.1 C83.1 C84.1 C85.1 C86.1 C87.1 C88.1 C89.1 R40.2 U2.E1(MID) U2.E2(MID) U2.F1(MID) U2.F2(MID) U2.G1(MID) U2.G2(MID) U2.G10(MID) U2.G11(MID) U2.G12(MID) U2.H1(MID) U2.H10(MID) U2.H11(MID) U2.H12(MID) U2.J10(MID) U2.J11(MID) U2.J12(MID)
N16684281: C90.2 U2.K3(TIMER)
N16684397: R38.1 U2.L11(HYS_PRGM)
N16684433: R39.1 U2.M11(FREQ)
N16684477: R29.2 R30.2 RN2.2 U2.K11(TEMP)
N16684533: R40.1 U2.H2(MID_SENSE)
N16684637: C180.2 E17.1 U2.J9(TEMP+)
N16684909: R41.1 U2.L10(COMPb)
N16687809: C104.1 C105.1 C106.1 C107.1 C108.1 C109.1 C110.1 C111.1 C112.1 C113.1 C114.1 C115.1 C116.1 U3.A6(C+) U3.B6(C+) U3.C6(C+) U3.D6(C+) U3.E6(C+) U3.F6(C+) U3.G5(C+) U3.G6(C+) U3.H5(C+) U3.H6(C+) U3.J6(C+) U3.K6(C+) U3.L6(C+) U3.M6(C+)
N16687853: R42.1 U3.F5(VIN_SNS)
N16688405: C104.2 C105.2 C106.2 C107.2 C108.2 C109.2 C110.2 C111.2 C112.2 C113.2 C114.2 C115.2 C116.2 U3.A8(C-) U3.A9(C-) U3.A10(C-) U3.A11(C-) U3.B8(C-) U3.B9(C-) U3.B10(C-) U3.B11(C-) U3.C8(C-) U3.C9(C-) U3.C10(C-) U3.C11(C-) U3.D8(C-) U3.E8(C-) U3.F8(C-) U3.G8(C-) U3.H8(C-) U3.J8(C-) U3.K8(C-) U3.L8(C-) U3.M8(C-)
N16688681: R43.2 U3.M3(MODE_PLLIN)
N16688717: R44.2 U3.M4(CLKOUT)
N16688737: C118.1 C119.1 C120.1 C121.1 C122.1 C123.1 C124.1 C125.1 C126.1 C127.1 C128.1 C129.1 C130.1 R48.2 U3.E1(MID) U3.E2(MID) U3.F1(MID) U3.F2(MID) U3.G1(MID) U3.G2(MID) U3.G10(MID) U3.G11(MID) U3.G12(MID) U3.H1(MID) U3.H10(MID) U3.H11(MID) U3.H12(MID) U3.J10(MID) U3.J11(MID) U3.J12(MID)
N16689047: C131.2 U3.K3(TIMER)
N16689163: R45.1 U3.L11(HYS_PRGM)
N16689199: R46.1 U3.M11(FREQ)
N16689243: R47.2 R50.2 RN3.2 U3.K11(TEMP)
N16689299: R48.1 U3.H2(MID_SENSE)
N16689403: C181.2 E19.1 U3.J9(TEMP+)
N16689675: R51.1 U3.L10(COMPb)
N16692574: C145.1 C146.1 C147.1 C148.1 C149.1 C150.1 C151.1 C152.1 C153.1 C154.1 C155.1 C156.1 C157.1 U4.A6(C+) U4.B6(C+) U4.C6(C+) U4.D6(C+) U4.E6(C+) U4.F6(C+) U4.G5(C+) U4.G6(C+) U4.H5(C+) U4.H6(C+) U4.J6(C+) U4.K6(C+) U4.L6(C+) U4.M6(C+)
N16692618: R52.1 U4.F5(VIN_SNS)
N16693170: C145.2 C146.2 C147.2 C148.2 C149.2 C150.2 C151.2 C152.2 C153.2 C154.2 C155.2 C156.2 C157.2 U4.A8(C-) U4.A9(C-) U4.A10(C-) U4.A11(C-) U4.B8(C-) U4.B9(C-) U4.B10(C-) U4.B11(C-) U4.C8(C-) U4.C9(C-) U4.C10(C-) U4.C11(C-) U4.D8(C-) U4.E8(C-) U4.F8(C-) U4.G8(C-) U4.H8(C-) U4.J8(C-) U4.K8(C-) U4.L8(C-) U4.M8(C-)
N16693446: R53.2 U4.M3(MODE_PLLIN)
N16693502: C159.1 C160.1 C161.1 C162.1 C163.1 C164.1 C165.1 C166.1 C167.1 C168.1 C169.1 C170.1 C171.1 R58.2 U4.E1(MID) U4.E2(MID) U4.F1(MID) U4.F2(MID) U4.G1(MID) U4.G2(MID) U4.G10(MID) U4.G11(MID) U4.G12(MID) U4.H1(MID) U4.H10(MID) U4.H11(MID) U4.H12(MID) U4.J10(MID) U4.J11(MID) U4.J12(MID)
N16693812: C172.2 U4.K3(TIMER)
N16693928: R55.1 U4.L11(HYS_PRGM)
N16693964: R56.1 U4.M11(FREQ)
N16694008: R57.2 R60.2 RN4.2 U4.K11(TEMP)
N16694064: R58.1 U4.H2(MID_SENSE)
N16694168: C182.2 E21.1 U4.J9(TEMP+)
N16702071: C179.2 E15.1 U1.J9(TEMP+)
N16721203: R61.1 U4.L10(COMPb)
N16724466: TP2.1(TP) U2.K4(TEST)
N16724501: TP3.1(TP) U3.K4(TEST)
N16724529: TP4.1(TP) U4.K4(TEST)
N16732560: R65.2 U4.M4(CLKOUT)
N16732568: E23.1 R65.1
N16813139: R62.2 R63.1
N16813143: C43.2 R15.1
N16837496: C177.2 C186.2

Not connected (* = marked no-connect by the designer): JP2 1*; MH1 1; MH2 1; MH3 1; MH4 1; MH5 1; MH6 1; MH7 1; MH8 1; MH9 1; MH10 1; SW1 4 5 6; U5 12(FBO)

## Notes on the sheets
sheet 1
- High Efficiency, PolyPhase, Hybrid Step-down µModule Bus Converter
sheet 2
- High Efficiency, PolyPhase, Hybrid Step-down µModule Bus Converter
sheet 3
- High Efficiency, PolyPhase, Hybrid Step-down µModule Bus Converter
sheet 4
- STANDOFFS
- High Efficiency, PolyPhase, Hybrid Step-down µModule Bus Converter
sheet 5
- +8V BIAS
- DYNAMIC LOAD CIRCUIT
- DO NOT EXCEED
- 2% DUTY CYCLE MAX.
- **
- VERSION
- IOUT
- U3
- U4
- C134,C135C136,C185
- C175,C176,C177,C186
- C132,C133
- C173,C174
- C105-C116, C119-C130
- C146-C157, C160-C171
- R19
- - A
- 50A
- OPT
- OPT
- OPT
- OPT
- OPT
- OPT
- OPT
- OPT
- 2.15K
- - B
- 75A
- LTM4660
- OPT
- 10uF
- OPT
- 150uF
- OPT
- 10uF
- OPT
- 1.43K
- - C
- 100A
- LTM4660
- LTM4660
- 10uF
- 10uF
- 150uF
- 150uF
- 10uF
- 10uF
- 1.07K
- High Efficiency, PolyPhase, Hybrid Step-down µModule Bus Converter
sheet 6
- REVISION HISTORY
- ECO
- REV
- DESCRIPTION
- DATE
- APPROVED
- -
- 2
- PRODUCTION
- 02/9/23
- HZ
- RUN
- ON
- OFF
- NOTES: UNLESS OTHERWISE SPECIFIED,
- High Efficiency, PolyPhase, Hybrid Step-down µModule Bus Converter
- 1.  CAPACITORS AND RESISTORS ARE 0603.
